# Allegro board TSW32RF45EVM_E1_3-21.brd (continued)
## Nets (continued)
TAA-: C2.2 L6.2 L13.1
TB+: C433.1 R9.2
TB-: C434.1 R10.2
TBB+: C10.1 L8.2 L11.1
TBB-: C10.2 L9.2 L12.1
U17_BYPASS: R157.1 R159.2
USBDM: C103.1 J11.2(D-) U5.16(USBDM)
USBDP: C104.1 J11.3(D+) U5.15(USBDP)
VCM: C61.1 TP2.1(TP) U1.22(VCM)
Y2_N: R80.1 R81.1 Y1.4(OUT_N)
Y2_P: R72.1 R73.1 Y1.5(OUT_P)
YO2_N: C84.1 R80.2
YO2_P: C81.1 R72.2
N19631466: C166.1 U12.14(NR)
N19631491: R127.2 U12.8(1P6V)
N19631493: R125.2 U12.11(0P2V)
N19631495: R124.2 U12.12(0P1V)
N19631505: R126.2 U12.10(0P4V)
N19879131: J11.4(ID) R96.2
N19879145: FB12.2 J11.1(VBUS)
N19879167: C101.1 C102.1 FB12.1 R95.2 TP4.1(TP) U5.20(VCC)
N19879302: U5.11(D3) U13.10(B4)
N19879304: U5.3(D2) U13.11(B3)
N19881704: J10.C18 R88.2
N19881714: J10.H2 R89.1
N19881723: D5.1(ANODE) R88.1
N19884870: C77.2 C78.2 C79.2 C80.2 FB1.1 Y1.6(VDD)
N19884947: SJP1.2(PIN2) Y1.2(NC)
N19886018: C9.1 R64.1 U3.16(DCLKOUT2N)
N19886020: C8.1 R63.1 U3.15(DCLKOUT2P)
N19887754: FB8.2 U3.42(VCC8_OSCIN)
N19887756: C93.2 C94.2 C95.2 FB6.2 FB7.1 FB8.1 FB9.1 U3.47(VCC10_PLL2)
N19887760: C98.2 FB10.2 U3.53(VCC11_CG3)
N19887762: C99.2 FB11.2 U3.64(VCC12_CG0)
N19887789: R86.2 U3.31(STATUS_LD1)
N19887795: R87.2 U3.48(STATUS_LD2)
N19887804: R85.2 U3.59(CLKIN_SEL1)
N19887822: R84.2 U3.58(CLKIN_SEL0)
N19887828: C96.1 U3.12(LDOBYP2)
N19887830: C97.1 U3.11(LDOBYP1)
N19887836: C87.2 C88.2 C89.2 FB2.2 U3.10(VCC1_VCO) U3.33(VCC5_DIG) U3.36(VCC6_PLL1)
N19887876: FB7.2 U3.39(VCC7_OSCOUT)
N19887878: FB9.2 U3.45(VCC9_CP2)
N19887910: C91.2 FB4.2 U3.21(VCC3_SYSREF)
N19887912: C90.2 FB3.2 U3.17(VCC2_CG1)
N19887930: C92.2 FB5.2 U3.26(VCC4_CG2)
N19893167: C372.1 T5.3(SEC)
N19893194: C373.1 T5.1(SEC DOT)
N19893222: C28.2 T5.4(PRI)
N19893438: C33.1 T5.2(NC)
N19895463: C372.2 U8.4(RF2)
N19895477: C373.2 U7.4(RF2)
N19955835: Q1.4(G) U15.4(GATE)
N20015888: C170.2 J13.1(CENTER)
N20015984: C171.2 J9.1(CENTER)
N20042801: R139.2 U16.7(200MV)
N20043120: R138.2 U16.6(100MV)
N20043460: R140.2 U16.9(400MV)
N20043630: R141.2 U16.10(800MV)
N20048856: R137.2 U16.4(PG)
N20080651: C368.1 SJP5.2(PIN2) U13.1(VCCA) U13.8(OE)
N20101312: R132.2 R134.1 U14.3(FB)
N20101314: L1.1 U14.6(SW)
N20101373: R136.2 U14.2(PG)
N20111831: R154.2 R155.1 U11.3(FB)
N20111833: L2.1 U11.6(SW)
N20111884: R153.2 U11.2(PG)
N20113513: C193.1 C197.1 R143.1 R158.2 U17.1(OUT4) U17.18(OUT1) U17.19(OUT2) U17.20(OUT3)
N20113515: C193.2 R143.2 R145.1 U17.16(FB/SNS)
N20114896: C204.1 FB19.1 L3.2 R146.1 R148.1 U18.4(VOS)
N20114915: R146.2 R147.1 U18.3(FB)
N20114917: L3.1 U18.6(SW)
N20114968: R148.2 U18.2(PG)
N20121078: FB17.1 R158.1 R159.1
N20150497: SJP2.2(PIN2) U16.14(EN)
N20151052: SJP3.2(PIN2) U17.11(EN)
N20152729: SJP4.2(PIN2) U18.1(EN)
N20210385: R40.2 R165.2 TP8.1(TP) U1.20(CTRL1)
N20210389: R40.1 R164.2 TP9.1(TP) U1.21(CTRL2)
N20213760: R33.2 SW1.1
N20220969: C387.1 U9.14(NR)
N20220990: R171.2 U9.8(1P6V)
N20220992: R172.2 U9.11(0P2V)
N20220994: R170.2 U9.12(0P1V)
N20221006: R173.2 U9.10(0P4V)
N20227487: C399.1 C400.2 U10.27(VBIASBANK)
N20231187: C403.2 U10.3(VBIASVCO)
N20232417: C404.2 U10.38(VREGVCO)
N20232915: C405.2 U10.29(VREFVCO#29)
N20233092: C406.2 U10.36(VREFVCO#36)
N20234062: C407.2 U10.33(VBIASVARAC)
N20235277: C409.1 R175.1 U10.23(RFOUTAP)
N20235286: C410.1 R176.1 U10.22(RFOUTAM)
N20237052: C412.1 R177.1 U10.18(RFOUTBP)
N20237066: C413.1 R178.1 U10.19(RFOUTBM)
N20239082: R179.2 U10.30(REXT)
N20249678: C391.2 U10.10(VCCIN)
N20251064: C394.2 R174.1
N20251377: C420.1 R182.2 R183.1
N20251505: C421.1 R183.2 U10.35(VTUNE)
N20257347: R184.1 R185.2 U10.20(MUXOUT)
N20258125: D7.1(ANODE) R185.1
N20306930: C429.1 U8.6(RFC)
N20306944: C430.1 U7.6(RFC)
N20361040: C36.1 U4.14(NR)
N20361065: R11.2 U4.12(0P1V)
N20361077: R12.2 U4.10(0P4V)
N20361858: R14.2 U4.6(3P2V)
N20361961: R13.2 U4.9(0P8V)
N20445187: C437.2 R6.2
N20459699: C433.2 L8.1
N20459721: C434.2 L9.1
N20459741: C435.2 L5.1
N20459761: C436.2 L6.1
N20460250: C438.2 R193.2
N20460913: C439.2 R194.2
N20461153: C440.2 R1.2
N183394940: D6.1(ANODE) R133.2
N198851401: C71.2 R54.1
N198852420: C70.2 R47.1

Pads without a net: J10 A22 A23 A26 A27 A30 A31 A34 A35 A38 A39 B1 B4 B5 B8 B9 B20 B21 B24 B25 B28 B29 B32 B33 B36 B37 B40 C2 C3 C10 C11 C14 C15 C19 C22 C23 C30 C31 C34 C35 C37 C39 D1 D8 D9 D11 D12 D14 D15 D17 D18 D20 D21 D23 D24 D26 D27 D29 D30 D31 D32 D33 D34 D35 D36 D38 D40 E2 E3 E6 E7 E9 E10 E12 E13 E15 E16 E18 E19 E21 E22 E24 E25 E27 E28 E30 E31 E33 E34 E36 E37 E39 F1 F4 F5 F7 F8 F10 F11 F13 F14 F16 F17 F19 F20 F22 F23 F25 F26 F28 F29 F31 F32 F34 F35 F37 F38 F40 G2 G3 G15 G16 G18 G19 G21 G22 G24 G25 G27 G28 G30 G31 G33 G34 G36 G37 G39 H1 H4 H5 H7 H8 H10 H11 H13 H14 H16 H17 H19 H20 H22 H23 H25 H26 H28 H29 H31 H32 H34 H35 H37 H38 H40 J2 J3 J6 J7 J9 J10 J12 J13 J15 J16 J18 J19 J21 J22 J24 J25 J27 J28 J30 J31 J33 J34 J36 J37 J39 K1 K4 K5 K7 K8 K10 K11 K13 K14 K16 K17 K19 K20 K22 K23 K25 K26 K28 K29 K31 K32 K34 K35 K37 K38 K40; U3 7 8 9 22 23 24 25 27 28 29 30 37 38 49 50 51 52 56 57 60 61; U4 2 4 5 8 11 17 18 19; U5 8 12 13 14 19 22 23 24 27 28; U9 2 4 5 6 9 17 18 19; U10 5 28 32; U12 2 4 5 6 9 17 18 19; U13 6 9; U15 1 3; U16 3 5 11 12 13; U17 2 3 4 9 13 14 15 17

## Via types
v1: diameter 0.457, hole 0.203, TOP to BOTTOM, 2207 vias
v2: diameter 0.305, hole 0.152, TOP to BOTTOM, 175 vias
v3: diameter 0.559, hole 0.305, TOP to BOTTOM, 511 vias
v4: diameter 0.508, hole 0.254, TOP to BOTTOM, 139 vias
v5: diameter 0.762, hole 0.381, TOP to BOTTOM, 8 vias
v6: diameter 0.61, hole 0.33, TOP to BOTTOM, 16 vias

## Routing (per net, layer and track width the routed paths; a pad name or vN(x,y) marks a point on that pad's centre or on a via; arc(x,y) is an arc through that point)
1.4V: length 24.1
  TOP w0.305: v1(75.16,4.98) 74.78,5.35 U11.4
  TOP w0.508: v1(75.16,4.98) 75.32,4.82 R154.1 v1(75.32,4.07) 75.55,3.84 v1(76.63,3.84)
  BOTTOM w0.432: 80.44,10.24 TP13.1 ; TP13.1 79.53,10.54 ; TP13.1 81.36,10.54 ; TP13.1 79.22,11.46 ; TP13.1 81.36,12.37 ; TP13.1 79.53,12.37 ; TP13.1 81.66,11.46 ; TP13.1 80.44,12.68
  BOTTOM w0.762: v1(76.3,11.23) 74.75,11.23 74.09,10.57 74.09,5.99 75.11,4.98 v1(75.16,4.98) 75.16,4.23 v1(75.32,4.07) 75.55,3.84 v1(76.63,3.84)
  vias: v1(76.33,14.12) v1(76.3,13.41) v1(76.33,12.74) v1(76.3,11.96) v1(77.22,14.12) v1(77.19,13.41) v1(77.22,12.74) v1(77.19,11.96) v1(77.19,11.23) v1(78.21,13.41) v1(78.21,11.96) v1(78.21,11.23) v1(78.23,14.12) v1(78.23,12.74) v1(84.2,15.67)
3.3VUSB: length 18.1
  BOTTOM w0.305: U13.14 50.69,24.99 49.33,24.99 48.16,23.83 48.16,21.21 47.72,20.77 U5.4
  BOTTOM w0.381: U5.17 40.29,15.57 v1(40.44,15.42) 40.72,15.42 44.63,19.33 44.63,20.39 45.01,20.77 U5.4
  vias: v1(50.72,24.96)
5.0V_IN: length 92.9
  TOP w0.127: v3(44.65,7.3) 44.65,8.27 v3(44.64,8.28) ; v3(44.65,7.3) v3(45.65,7.3) ; v3(44.65,7.3) v3(43.65,7.3) ; v3(45.65,7.3) v3(46.65,7.3) v3(46.65,8.3) ; v3(45.65,7.3) v3(45.65,8.3) ; v3(46.65,8.3) v3(45.65,8.3) ; v3(46.65,8.3) v3(46.65,9.3) ; v3(45.65,8.3) 45.63,8.28 v3(44.64,8.28) ; v3(45.65,8.3) v3(45.65,9.3) ; v3(42.65,8.3) v3(42.65,7.3) v3(43.65,7.3) ; v3(42.65,8.3) v3(42.65,9.3) ; v3(42.65,8.3) v3(43.65,8.3) ; v3(46.65,9.3) 46.56,9.39 Q1.5 ; v3(46.65,9.3) v3(45.65,9.3) ; v3(44.64,8.28) 44.62,8.3 v3(43.65,8.3) ; v3(44.64,8.28) 44.64,9.29 v3(44.65,9.3) ; v3(43.65,7.3) v3(43.65,8.3) ; v3(42.65,9.3) 42.75,9.39 Q1.8 ; v3(42.65,9.3) v3(43.65,9.3) ; v3(43.65,9.3) v3(44.65,9.3) ; v3(43.65,9.3) v3(43.65,8.3) ; v3(45.65,9.3) v3(44.65,9.3)
  TOP w0.432: TP17.1 41.04,7.73 ; TP17.1 38.67,10.1 ; TP17.1 41.45,8.92 ; TP17.1 38.25,8.92 ; TP17.1 39.85,7.31 ; TP17.1 41.04,10.1 ; TP17.1 38.67,7.73 ; TP17.1 39.85,10.52 ; 34.92,5.44 J8.1 ; J8.1 33.04,6.14 ; J8.1 36.81,6.14 ; J8.1 32.33,8.03 ; J8.1 37.52,8.03 ; J8.1 33.04,9.91 ; J8.1 34.92,10.62 ; J8.1 36.81,9.91
  BOTTOM w0.432: J8.1 34.92,10.62 ; J8.1 33.04,9.91 ; J8.1 33.04,6.14 ; J8.1 37.52,8.03 ; J8.1 32.33,8.03 ; J8.1 36.81,9.91 ; J8.1 34.92,5.44 ; J8.1 36.81,6.14 ; 38.67,7.73 TP17.1 ; TP17.1 39.85,7.31 ; TP17.1 38.67,10.1 ; TP17.1 38.25,8.92 ; TP17.1 41.04,10.1 ; TP17.1 39.85,10.52 ; TP17.1 41.45,8.92 ; TP17.1 41.04,7.73
5VIN: length 13.1
  TOP w0.305: U14.1 58.22,6.65 U14.7 58.35,6.8 57.66,7.49 ; U18.7 97.34,10.59 C203.1 ; U11.1 73.28,6.25 73.43,6.4 U11.7 73.43,9.22 C121.1
  BOTTOM w0.254: 131.95,4.45 131.9,4.5
  BOTTOM w0.305: U12.13 123.39,4.75 123.22,4.57 ; U17.10 v1(83.13,14.41) ; 131.9,4.5 131.9,5.78 U4.13
  vias: v1(35.46,16.08) v1(35.46,15.32) v1(36.12,16.08) v1(36.12,15.32) v1(36.8,16.08) v1(36.78,15.32) v1(56.97,8.31) v1(56.97,7.47) v1(56.97,6.68) v1(57,5.77) v1(56.97,4.93) v1(57.04,9.15) v1(57.91,8.31) v1(57.91,7.47) v1(57.91,6.68) v1(57.91,5.77) v1(57.89,4.93) v1(57.93,9.15) v1(72.19,9.6) v1(72.19,8.71) v1(72.19,7.87) v1(72.19,7.09) v1(72.19,6.22) v1(72.16,5.38) v1(73.03,8.71) v1(73.03,7.87) v1(73.03,7.09) v1(73.03,6.22) v1(73,5.38) v1(73.05,9.58) v1(81.2,13.74) v1(94.77,5.79) v1(95.4,11) v1(95.4,10.11) v1(95.4,9.22) v1(95.4,8.33) v1(96.11,8.38) v1(96.18,10.98) v1(96.16,10.11) v1(96.16,9.22) v1(96.82,8.38) v1(96.9,10.98) v1(96.93,10.11) v1(96.93,9.22) v1(106.5,7.82) v1(106.5,7.16) v1(106.48,6.48) v1(107.16,8.33) v1(107.16,7.67) v1(107.14,6.99) v1(107.14,6.27) v1(107.82,6.5) v1(107.85,7.85) v1(107.85,7.19) v1(119.18,6.5) v1(119.18,5.84) v1(119.15,5.16) v1(119.81,5.66) v1(119.81,4.95) v1(119.84,7.01) v1(119.84,6.35) v1(120.52,6.53) v1(120.52,5.87) v1(120.5,5.18) v1(128.83,5.61) v1(128.83,4.95) v1(128.8,4.27) v1(129.49,6.12) v1(129.49,5.46) v1(129.46,4.78) v1(129.46,4.06) v1(130.18,5.64) v1(130.18,4.98) v1(130.15,4.29) v3(42.6,3.91) v3(42.6,3.12) v3(42.72,5.49) v3(42.7,4.72) v3(43.51,5.49) v3(43.51,4.72) v3(43.54,3.91) v3(43.54,3.12) v3(44.32,4.72) v3(44.37,5.49) v3(44.37,3.91) v3(44.37,3.12) v3(45.29,5.51) v3(45.26,4.7) v3(45.26,3.91) v3(45.26,3.12) v3(50.72,3.84) v3(50.75,4.83) v3(51.64,4.83) v3(51.64,3.84) v3(52.53,4.83) v3(52.53,3.84)
+1.9V: length 8.2
  TOP w0.508: FB20.3 62.61,27.69 62.18,28.12 SJP5.3
+2.2V: length 33.9
  TOP w0.305: v1(60.07,4.5) 59.72,4.85 U14.4
  TOP w0.432: TP15.1 64.06,14.25 ; TP15.1 63.15,12.12 ; TP15.1 62.84,13.03 ; TP15.1 64.06,11.81 ; TP15.1 63.15,13.94 ; TP15.1 65.28,13.03 ; TP15.1 64.97,12.12 ; TP15.1 64.97,13.94
  TOP w0.508: v1(60.07,4.5) 60.2,4.37 v1(60.2,3.66) ; v1(60.2,3.66) v1(60.71,3.66) ; v1(60.2,3.66) 60.23,3.69 v1(61.28,3.69)
  BOTTOM w0.432: TP15.1 64.06,14.25 ; TP15.1 64.97,13.94 ; TP15.1 63.15,12.12 ; TP15.1 63.15,13.94 ; TP15.1 64.97,12.12 ; TP15.1 65.28,13.03 ; TP15.1 64.06,11.81 ; TP15.1 62.84,13.03
  BOTTOM w0.762: v1(61.09,10.92) 59.69,10.92 58.9,10.13 58.9,6.38 60.07,5.21 v1(60.07,4.5) 60.2,4.37 v1(60.2,3.66) v1(60.71,3.66) 60.73,3.69 v1(61.28,3.69)
  vias: v1(61.09,13.97) v1(61.09,13.21) v1(61.09,12.45) v1(61.09,11.68) v1(61.85,13.97) v1(61.85,13.21) v1(61.85,12.45) v1(61.85,11.68) v1(61.85,10.92) v1(62.61,13.97) v1(62.61,13.21) v1(62.61,12.45) v1(62.61,11.68) v1(62.61,10.92) v1(65.38,15.04)
+3.3V_LMX: length 26.3
  TOP w0.305: v2(55.35,61.7) v2(54.64,61.7) ; v2(58.78,64.11) 58.76,64.12 v2(58.76,64.47) 58.75,64.48 v2(58.75,64.85) ; v2(55.35,59.18) 55.34,59.19 v2(54.99,59.19) 54.65,59.19 v2(54.64,59.18) ; v2(61.39,60.68) v2(60.68,60.68) ; v2(60.25,58.72) v2(60.25,58.39) v2(60.25,58.06)
  TOP w0.432: 113.77,24.05 TP10.1 ; TP10.1 112.85,24.36 ; TP10.1 113.77,26.49 ; TP10.1 114.68,26.19 ; TP10.1 112.55,25.27 ; TP10.1 114.99,25.27 ; TP10.1 112.85,26.19 ; TP10.1 114.68,24.36
  TOP w0.508: C398.2 58.17,58.6 58.17,57.79 v1(58.62,57.43)
  L3_PWR w0.432: 112.85,26.19 TP10.1 ; TP10.1 112.55,25.27 ; TP10.1 114.99,25.27 ; TP10.1 114.68,24.36 ; TP10.1 112.85,24.36 ; TP10.1 113.77,24.05 ; TP10.1 114.68,26.19 ; TP10.1 113.77,26.49
  BOTTOM w0.305: v1(58.62,57.43) 58.26,57.79 v2(58.26,58.42)
  vias: v1(64.29,63.7) v1(112.27,25.78) v1(112.27,24.89) v1(112.27,24) v1(112.39,26.8) v1(113.28,26.8) v1(114.68,26.67) v1(115.57,26.67) v1(115.57,25.78) v1(115.57,24.89) v1(116.46,26.67) v1(116.46,25.78) v2(54.99,61.69) v2(58.27,58.78) v2(61.04,60.69)
+3.3V_LMXRF: length 1.5
  TOP w0.305: v2(56.03,56.18) 56.08,56.13 C411.1 56.9,56.13 v2(56.95,56.18)
  BOTTOM w0.305: R178.2 v2(56.03,56.18) ; R177.2 v2(56.95,56.18) v1(56.49,56.18)
  vias: v1(38.61,62.13) v1(38.61,61.37) v1(39.24,62.33) v1(39.88,62.13) v1(39.88,61.37) v1(53.06,59.92) v1(109.09,25.15) v1(109.09,24.26) v1(109.09,23.37) v1(109.98,25.15) v1(109.98,24.26) v1(109.98,23.37) v1(110.87,25.15) v1(110.87,24.26) v1(110.87,23.37) v2(53.06,60.38) v2(53.06,59.46)
+3.3VCLK: length 28.9
  TOP w0.432: TP12.1 127.15,21.61 ; TP12.1 126.24,21.92 ; TP12.1 125.02,20.7 ; TP12.1 125.32,19.79 ; TP12.1 127.15,19.79 ; TP12.1 125.32,21.61 ; TP12.1 126.24,19.48
  L6_PWR w0.432: TP12.1 126.24,21.92 ; TP12.1 126.24,19.48 ; TP12.1 127.46,20.7 ; TP12.1 125.32,21.61 ; TP12.1 127.15,21.61 ; TP12.1 125.02,20.7 ; TP12.1 125.32,19.79 ; TP12.1 127.15,19.79
  BOTTOM w0.432: TP12.1 127.15,19.79 ; TP12.1 127.15,21.61 ; TP12.1 125.32,21.61 ; TP12.1 126.24,19.48 ; TP12.1 126.24,21.92 ; TP12.1 127.46,20.7 ; TP12.1 125.02,20.7 ; TP12.1 125.32,19.79
  vias: v1(86.41,54.33) v1(86.39,53.59) v1(86.74,58.67) v1(86.74,58.04) v1(86.74,55.6) v1(86.74,54.99) v1(87.1,54.33) v1(87.07,53.59) v1(87.38,58.67) v1(87.38,58.06) v1(87.38,55.6) v1(87.38,54.99) v1(91.11,64.77) v1(91.14,65.46) v1(91.72,64.74) v1(91.74,65.46) v1(92.3,65.48) v1(92.28,64.72) v1(100.51,60.58) v1(100.48,60.03) v1(100.53,61.19) v1(100.53,52.37) v1(101.22,61.17) v1(101.22,60.56) v1(101.24,60) v1(101.83,52.98) v1(101.78,51.82) v1(102.41,52.98) v1(102.41,52.37) v1(102.44,51.82) v1(103.54,65.42) v1(103.54,63.17) v1(111.56,65.76) v1(111.56,64.9) v1(112.14,65.33) v1(112.7,65.76) v1(112.7,64.9) v1(118.24,58.7) v1(123.57,22.73) v1(123.57,22.1) v1(123.57,21.46) v1(124.21,22.73) v1(124.21,22.1) v1(124.21,21.46) v1(124.84,22.73) v1(124.84,22.1) v1(124.84,21.46) v1(125.48,22.73) v1(125.48,22.1)
+4.5V: length 19.6
  TOP w0.508: L14.1 v1(23.62,37.34) ; L4.1 v1(23.62,48.13)
  L6_PWR w0.432: 133.07,21.61 TP1.1 ; TP1.1 133.99,19.48 ; TP1.1 134.9,21.61 ; TP1.1 132.77,20.7 ; TP1.1 134.9,19.79 ; TP1.1 133.99,21.92 ; TP1.1 133.07,19.79 ; TP1.1 135.2,20.7
  BOTTOM w0.432: TP1.1 134.9,21.61 ; TP1.1 133.07,21.61 ; TP1.1 133.99,21.92 ; TP1.1 134.9,19.79 ; TP1.1 133.99,19.48 ; TP1.1 133.07,19.79 ; TP1.1 132.77,20.7
  vias: v1(21.34,46.48) v1(21.34,38.99) v1(131.32,23.75) v1(131.32,23.24) v1(131.57,22.35) v1(131.72,21.36) v1(131.65,18.9) v1(131.65,18.08) v1(131.83,20.17) v1(132.21,18.9) v1(132.21,18.08) v1(132.33,23.5) v1(132.46,22.73) v1(132.46,22.1) v1(132.46,21.34) v1(133.48,23.5) v1(133.48,22.73) v1(133.48,22.1) v1(133.68,18.9) v1(133.68,18.08) v1(134.24,24.51) v1(134.24,23.5) v1(134.24,22.73) v1(134.24,18.9) v1(134.24,18.08) v1(134.87,24.51) v1(134.87,23.5) v1(134.87,22.1)
AVDD1.9V: length 49.5
  TOP w0.254: U1.39 38.99,37.14 v2(38.84,36.98) v2(38.53,36.68) 38.53,36.32 v1(38.58,36.37) ; U1.24 v2(36.88,44.49) 35.88,44.49 v1(35.81,44.55) ; v2(41.99,37.36) U1.45 41.99,37.97 v2(41.96,38) ; v1(35.79,40.84) 35.94,41 v2(36.22,41) U1.31 ; v1(38.79,49.07) 38.99,48.87 v2(38.99,48.69) U1.16 ; v2(42.21,48.46) 41.99,48.24 U1.10 ; v2(42.57,36.78) v1(42.57,36.27)
  TOP w0.305: v1(41.94,49.2) 42.21,48.92 v2(42.21,48.82) v2(42.21,48.46) ; v2(41.99,37.36) v1(42.26,37.08) v2(42.27,37.08) v2(42.57,36.78)
  TOP w0.432: 65.66,22.28 TP20.1 ; TP20.1 65.66,24.71 ; TP20.1 64.44,23.5 ; TP20.1 66.57,22.58 ; TP20.1 66.88,23.5 ; TP20.1 64.75,24.41 ; TP20.1 66.57,24.41 ; TP20.1 64.75,22.58
  L3_PWR w0.432: 64.75,24.41 TP20.1 ; TP20.1 64.44,23.5 ; TP20.1 66.57,22.58 ; TP20.1 66.57,24.41 ; TP20.1 66.88,23.5 ; TP20.1 64.75,22.58 ; TP20.1 65.66,22.28 ; TP20.1 65.66,24.71
  BOTTOM w0.305: v2(37.49,44.49) v2(36.88,44.49) 36.36,44.49 v2(36.35,44.5) 35.86,44.5 v1(35.81,44.55) ; v1(41.94,49.2) 42.21,48.92 v2(42.21,48.82) v2(42.21,48.46) ; v1(42.57,36.27) v2(42.57,36.78) v2(42.27,37.08) v1(42.26,37.08) v2(41.99,37.36) 41.96,37.39 v2(41.96,38) ; v1(38.58,36.37) 38.53,36.32 v2(38.53,36.68) v2(38.84,36.98) 38.99,37.13 v2(38.99,37.49) v2(38.99,38) ; v1(35.79,40.84) 35.94,41 v2(36.22,41) v2(36.63,41) v2(37.08,41) v2(37.49,41) ; v1(38.79,49.07) 38.99,48.87 v2(38.99,48.69) v2(38.99,48.26)
  BOTTOM w0.432: 64.44,23.5 TP20.1 ; TP20.1 66.57,22.58 ; TP20.1 64.75,24.41 ; TP20.1 66.88,23.5 ; TP20.1 65.66,22.28 ; TP20.1 66.57,24.41 ; TP20.1 64.75,22.58 ; TP20.1 65.66,24.71
  vias: v1(33.91,38.86) v1(33.91,36.63) v1(62.48,24.38) v1(62.48,23.62) v1(62.48,22.86) v1(62.48,22.1) v1(63.25,24.38) v1(63.25,23.62) v1(63.25,22.86) v1(63.25,22.1) v1(64.01,24.38) v1(64.01,23.62) v1(64.01,22.86) v1(64.01,22.1)
AVDD1.15V: length 49.6
  TOP w0.254: v1(37.82,36.37) v2(37.82,36.65) ; U1.30 v2(36.25,41.48) 35.92,41.48 v1(35.79,41.61) ; v1(42.7,49.2) 42.72,49.17 v2(42.72,48.79) ; v2(41.81,36.73) v1(41.81,36.27) ; U1.38 v2(38.49,37.56) 37.93,36.98 v2(37.82,36.98) ; U1.44 v2(41.49,37.05) ; U1.46 v2(42.49,38.07) ; U1.25 v2(36.88,43.99) 36.01,43.99 v1(35.81,43.79) ; v2(42.7,48.41) 42.7,48.36 42.49,48.15 U1.9
  TOP w0.305: U1.17 v2(38.49,48.17) v2(38.02,48.64) v1(38.02,49.07) ; v2(42.7,48.41) 42.72,48.44 v2(42.72,48.79) ; v2(37.82,36.65) v2(37.82,36.98) ; v2(41.49,37.05) v2(41.81,36.73)
  L6_PWR w0.152: v2(42.49,38.07) 42.49,38.18 42.8,38.48 42.8,39.37
  L6_PWR w0.305: v2(42.49,38.07) v2(42.49,37.69)
  L6_PWR w0.432: TP22.1 85.65,23.14 ; TP22.1 83.21,23.14 ; TP22.1 84.43,24.36 ; TP22.1 85.34,24.06 ; TP22.1 83.51,24.06 ; TP22.1 83.51,22.23 ; TP22.1 85.34,22.23 ; TP22.1 84.43,21.92
  BOTTOM w0.305: v2(38.48,37.97) 38.49,37.96 v2(38.49,37.56) 38.49,37.55 v2(38.2,37.26) 37.92,36.98 v2(37.82,36.98) v2(37.82,36.65) v1(37.82,36.37) ; 41.24,37.3 41.28,37.34 41.28,37.97 ; 41.24,37.3 v2(41.49,37.05) ; 41.24,37.3 41.02,37.52 v2(41.02,37.69) 41.02,38 41.05,37.97 41.28,37.97 ; v2(37.49,43.99) v2(36.88,43.99) 36.88,43.99 v2(36.35,43.99) 36.02,43.99 v1(35.81,43.79) ; 41.28,37.97 v2(41.48,37.97) v2(41.48,37.49) 41.49,37.48 v2(41.49,37.05) ; v2(41.49,37.05) v2(41.81,36.73) v1(41.81,36.27) ; v1(35.79,41.61) 35.92,41.48 v2(36.25,41.48) v2(36.7,41.48) v2(37.11,41.48) v2(37.49,41.48) ; 39.55,47.47 38.89,47.47 38.49,47.87 v2(38.49,48.17) v2(38.02,48.64) v1(38.02,49.07) ; 39.55,47.47 40.97,47.47 41,47.45 v2(41,47.78) v2(39.5,47.78) 39.5,47.52 39.55,47.47 ; v2(42.49,37.69) 42.49,38.05 C47.1 ; v2(39.47,37.67) 39.47,38.02 v2(39.52,38.07) ; v1(42.7,49.2) 42.72,49.17 v2(42.72,48.79) 42.7,48.77 v2(42.7,48.41)
  BOTTOM w0.432: 83.51,22.23 TP22.1 ; TP22.1 83.21,23.14 ; TP22.1 83.51,24.06 ; TP22.1 85.34,22.23 ; TP22.1 85.34,24.06 ; TP22.1 85.65,23.14 ; TP22.1 84.43,21.92 ; TP22.1 84.43,24.36
  vias: v1(83.16,21.49) v1(84.05,21.49) v1(84.94,21.49) v1(85.98,23.27) v1(85.95,22.38) v1(85.95,21.49) v1(86.87,23.27) v1(86.84,22.38) v1(86.84,21.49) v2(39.55,47.42) v2(41,47.4) v2(41,38.07)
DVDD1.15V: length 82.3
  TOP w0.254: v1(43.46,49.2) 43.41,49.15 v2(43.41,48.77) ; v2(43.38,48.36) 42.99,47.97 U1.8 ; v2(45.34,48.26) 44.99,47.91 U1.4 ; v1(43.33,36.27) v2(43.33,36.7) ; v2(43.18,37.34) 42.99,37.53 v2(42.99,37.84) ; U1.64 v2(46.89,42.98)
  TOP w0.305: v1(45.44,49.07) 45.38,49.01 45.38,48.73 45.34,48.69 v2(45.34,48.62) v2(45.34,48.26) ; v2(46.89,46) U1.70 47.84,45.99 v1(47.85,45.97) ; U1.51 44.99,37.38 v2(45.19,37.19) v2(45.19,36.78) 45.19,36.3 v1(45.21,36.27) ; v2(43.33,36.7) 43.18,36.86 v2(43.18,37.01) v2(43.18,37.34) ; v2(43.38,48.36) 43.41,48.39 v2(43.41,48.77)
  TOP w0.381: v1(47.78,42.98) v2(47.29,42.98) v2(46.89,42.98) ; U1.57 v2(46.95,39.49)
  TOP w0.432: TP5.1 100.43,20.65 ; TP5.1 99.52,20.34 ; TP5.1 99.52,22.78 ; TP5.1 100.74,21.56 ; TP5.1 98.6,20.65 ; TP5.1 98.6,22.48 ; TP5.1 100.43,22.48 ; TP5.1 98.3,21.56
  TOP w0.762: v1(98.42,20.12) 98.22,20.32 94.23,20.32 92.2,18.29 92.2,8.64 90.93,7.37 88.27,7.37 86.74,5.84 v1(84.48,5.84)
  L6_PWR w0.305: v2(43.18,37.34) 43.18,37.65 v2(42.99,37.84) 43.3,37.84 43.56,38.1
  L6_PWR w0.432: 98.6,22.48 TP5.1 ; TP5.1 99.52,20.34 ; TP5.1 100.43,22.48 ; TP5.1 99.52,22.78 ; TP5.1 100.74,21.56 ; TP5.1 100.43,20.65 ; TP5.1 98.6,20.65 ; TP5.1 98.3,21.56 ; JP1.1 93.98,27.97 ; JP1.1 92.81,26.8 ; JP1.1 93.1,25.92 ; JP1.1 95.15,26.8 ; JP1.1 94.86,25.92 ; JP1.1 93.98,25.63 ; JP1.1 93.1,27.67 ; JP1.1 94.86,27.67
  BOTTOM w0.305: v2(46.89,42.98) v2(47.29,42.98) ; v2(43.38,48.36) 43.38,48.74 v2(43.41,48.77) 43.41,49.15 v1(43.46,49.2) ; v2(45.34,48.26) v2(45.34,48.62) 45.34,48.97 v1(45.44,49.07) ; v1(45.21,36.27) 45.19,36.3 v2(45.19,36.78) v2(45.19,37.19) ; v2(42.99,37.84) 42.99,37.53 v2(43.18,37.34) v2(43.18,37.01) 43.18,36.86 v2(43.33,36.7) v1(43.33,36.27)
  BOTTOM w0.381: v2(47.29,39.5) 47.28,39.49 v2(46.95,39.49) ; v2(47.29,42.98) v1(47.78,42.98) ; v1(47.85,45.97) v2(47.29,45.97) 46.91,45.97 v2(46.89,46)
  BOTTOM w0.432: 99.52,20.34 TP5.1 ; TP5.1 100.74,21.56 ; TP5.1 99.52,22.78 ; TP5.1 98.6,20.65 ; TP5.1 98.6,22.48 ; TP5.1 98.3,21.56 ; TP5.1 100.43,22.48 ; TP5.1 100.43,20.65
  vias: v1(44.27,35.13) v1(44.35,50.18) v1(53.24,27.48) v1(53.24,26.8) v1(53.9,27.48) v1(53.9,26.8) v1(98.4,19.3) v1(98.4,18.49) v1(99.21,19.3) v1(99.21,18.49) v1(99.24,20.12) v1(100.08,20.12) v1(100.05,19.3) v1(100.05,18.49)
GND: length 2671.2
  TOP w0.127: 46.64,44.49 U1.67 ; v3(43.56,44.05) v3(42.24,42.74) ; v3(46.19,40.11) v3(44.87,40.11) ; v3(40.93,41.42) 39.99,40.49 U1.32 ; 39.99,44.99 v3(40.93,44.05) ; 45.47,38.48 45.49,38.46 ; 45.49,45.99 v3(44.87,45.37)
  TOP w0.152: U8.2 v2(32.64,44.53)
  TOP w0.203: v3(46.19,38.79) 47.23,37.74 v1(47.37,37.74) ; 46.61,44.45 46.64,44.49 ; U1.26 41.49,43.49 v3(42.24,42.74) 41.49,41.99 U1.29 ; v2(32.64,44.53) 32.72,44.53 32.77,44.48 33.2,44.48 ; 45.49,38.46 U1.52 ; 32.44,41.81 v2(31.83,41.81) ; U1.3 45.49,45.99 ; U1.23 39.99,44.99
  TOP w0.254: U1.18 37.99,46.99 v3(38.3,46.68) ; U1.60 v1(47.84,40.99) 48.65,40.99 v1(48.95,40.69) ; U1.37 37.99,38.49 v3(38.3,38.79)
  TOP w0.305: C397.2 55.96,59.39 v6(56.49,59.92) ; U2.3 19.68,42.99 v4(19.43,42.74) 19.68,42.49 U2.4 ; v3(38.3,38.79) v3(39.61,40.11) ; v6(56.49,61.95) 56.36,61.95 56.11,61.7 C390.1 ; v3(38.3,46.68) v3(39.61,45.37) ; v1(98.96,9.35) 98.7,9.35 98.54,9.18 U18.5 ; U2.19 23.86,45.32 v2(24.13,45.59) ; U11.5 v1(75.09,7.3) ; U11.5 74.63,6.72 74.78,6.58 v1(75.03,6.58) ; U11.5 74.63,7.88 74.75,8 v1(75.06,8) ; U2.16 25.53,42.99 v4(25.78,42.74) 25.53,42.49 U2.15 ; U2.12 23.86,40.18 v2(24.13,39.9) ; U2.7 v2(21.36,39.9) 21.86,40.4 U2.8 ; U2.24 v2(21.36,45.57) 21.86,45.07 U2.23 ; U14.5 59.68,6.91 v1(59.97,6.91) ; v6(59.54,60.93) 59.79,60.68 C392.2 ; v1(59.97,6.91) v1(59.97,6.4) 59.66,6.71 59.66,7.14 59.94,7.42 v1(59.94,7.44) 59.97,7.42 v1(59.97,6.91) ; v6(59.54,62.97) 59.05,63.45 C401.2 v6(58.52,62.97) ; C94.1 v1(95.91,67.41) ; v1(43.46,49.91) 43.41,49.86 C37.2 41.99,49.86 v1(41.94,49.91) ; U18.5 v1(99.03,8.66) ; U18.5 98.54,8.12 98.7,7.95 v1(98.96,7.95)
  TOP w0.381: R89.2 139.98,58.91 v1(139.7,59.18) ; v1(43.33,35.56) v1(42.57,35.56) v1(41.81,35.56)
  TOP w0.432: 26.34,8.03 J8.2 ; J8.2 31.01,8.03 ; J8.2 30.38,9.73 ; J8.2 30.38,6.32 ; J8.2 28.68,10.36 ; J8.2 26.97,6.32 ; J8.2 28.68,5.69 ; 22.35,29.82 JP5.2 ; JP5.2 23.52,30.99 ; JP5.2 21.47,30.11 ; JP5.2 21.18,30.99 ; JP5.2 23.23,30.11 ; JP5.2 22.35,32.16 ; JP5.2 23.23,31.87 ; JP5.2 21.47,31.87 ; 71.75,66.89 J7.3 ; J7.3 72.97,67.32 ; J7.3 74.2,64.43 ; J7.3 74.64,65.66 ; J7.3 74.2,66.89 ; J7.3 71.75,64.43 ; J7.3 71.31,65.66 ; J7.3 72.97,63.99 ; 48.01,65.05 JP2.1 ; JP2.1 49.17,65.05 ; JP2.1 46.84,67.39 ; JP2.1 48.01,67.39 ; JP2.1 46.84,65.05 ; JP2.1 49.17,67.39 ; JP2.1 49.17,66.22 ; JP2.1 46.84,66.22 ; 16.17,19.39 MT2.1 ; MT2.1 19.99,17.78 ; MT2.1 15.57,17.78 ; MT2.1 17.78,15.57 ; MT2.1 19.39,16.17 ; MT2.1 16.17,16.17 ; MT2.1 17.78,19.99 ; MT2.1 19.39,19.39 ; J9.3 133.37,56.16 ; J9.3 131.03,54.56 ; J9.3 134.29,55.24 ; J9.3 132.01,52.96 ; J9.3 131.46,53.33 ; J9.3 132.69,56.22 ; J9.3 133.92,55.79 ; J9.3 131.09,53.88 ; J9.3 132.01,56.16 ; J9.3 133.37,52.96 ; J9.3 134.29,53.88 ; J9.3 133.92,53.33 ; J9.3 131.09,55.24 ; J9.3 134.35,54.56 ; J9.3 132.69,52.89 ; J9.3 131.46,55.79 ; 126.93,47.88 J9.5 ; J9.5 129.27,49.48 ; J9.5 126.38,50.71 ; J9.5 129.21,50.16 ; J9.5 125.95,49.48 ; J9.5 126.01,50.16 ; J9.5 128.29,47.88 ; J9.5 126.01,48.8 ; J9.5 127.61,47.81 ; J9.5 126.38,48.25 ; J9.5 126.93,51.08 ; J9.5 129.21,48.8 ; J9.5 127.61,51.14 ; J9.5 128.29,51.08 ; J9.5 128.84,50.71 ; J9.5 128.84,48.25 ; J9.4 134.35,49.48 ; J9.4 131.03,49.48 ; J9.4 131.46,48.25 ; J9.4 131.46,50.71 ; J9.4 132.69,47.81 ; J9.4 132.69,51.14 ; J9.4 133.92,50.71 ; TP11.1 117.25,4.34 ; TP11.1 116.33,4.65 ; TP11.1 117.55,3.43 ; TP11.1 117.25,2.52 ; TP11.1 115.42,2.52 ; TP11.1 115.42,4.34 ; TP11.1 116.33,2.21 ; TP11.1 115.11,3.43 ; 17.06,66.51 MT1.1 ; MT1.1 18.67,67.11 ; MT1.1 20.28,63.28 ; MT1.1 20.88,64.9 ; MT1.1 16.46,64.9 ; MT1.1 18.67,62.69 ; MT1.1 17.06,63.28 ; MT1.1 20.28,66.51 ; 40.94,63.35 JP3.2 ; JP3.2 42.11,62.18 ; JP3.2 42.99,62.47 ; JP3.2 41.24,64.22 ; JP3.2 42.99,64.22 ; JP3.2 42.11,64.52 ; JP3.2 43.28,63.35 ; JP3.2 41.24,62.47 ; 122.48,26.16 TP19.1 ; TP19.1 124.92,26.16 ; TP19.1 122.78,25.25 ; TP19.1 122.78,27.08 ; TP19.1 123.7,24.94 ; TP19.1 123.7,27.38 ; TP19.1 124.61,25.25 ; TP19.1 124.61,27.08 ; 99.06,25.63 JP1.3 ; JP1.3 98.18,27.67 ; JP1.3 100.23,26.8 ; JP1.3 99.94,27.67 ; JP1.3 99.06,27.97 ; JP1.3 99.94,25.92 ; JP1.3 97.89,26.8 ; JP1.3 98.18,25.92 ; 131.03,60.27 J13.4 ; J13.4 133.92,61.5 ; J13.4 132.69,61.94 ; J13.4 133.92,59.05 ; J13.4 131.46,61.5 ; J13.4 132.69,58.61 ; J13.4 131.46,59.05 ; J13.4 134.35,60.27 ; 103.81,22.61 TP6.1 ; TP6.1 104.12,23.52 ; TP6.1 104.12,21.69 ; TP6.1 105.94,21.69 ; TP6.1 106.25,22.61 ; TP6.1 105.94,23.52 ; TP6.1 105.03,21.39 ; TP6.1 105.03,23.83 ; 31.93,0.89 J8.3 ; J8.3 34.27,3.23 ; J8.3 30.22,1.52 ; J8.3 33.63,1.52 ; J8.3 30.22,4.93 ; J8.3 29.59,3.23 ; J7.4 74.2,59.35 ; J7.4 71.75,61.81 ; J7.4 71.31,60.58 ; J7.4 74.2,61.81 ; J7.4 72.97,62.24 ; J7.4 71.75,59.35 ; J7.4 74.64,60.58 ; 21.18,54.48 22.35,54.48 ; 22.35,54.48 22.35,55.65 ; 22.35,54.48 23.23,55.36 ; 22.35,54.48 21.47,53.61 ; 22.35,54.48 23.23,53.61 ; 22.35,54.48 21.47,55.36 ; 22.35,54.48 23.52,54.48 ; 22.35,54.48 22.35,53.31 ; TP21.1 73.63,22.96 ; TP21.1 71.5,22.05 ; TP21.1 71.81,21.13 ; TP21.1 72.72,23.27 ; TP21.1 73.63,21.13 ; TP21.1 72.72,20.83 ; TP21.1 71.81,22.96 ; TP21.1 73.94,22.05 ; J9.2 129.21,53.88 ; J9.2 129.21,55.24 ; J9.2 128.84,53.33 ; J9.2 129.27,54.56 ; J9.2 128.84,55.79 ; J9.2 127.61,56.22 ; J9.2 126.38,55.79 ; J9.2 126.38,53.33 ; J9.2 126.01,53.88 ; J9.2 128.29,56.16 ; J9.2 125.95,54.56 ; J9.2 126.93,52.96 ; J9.2 126.01,55.24 ; J9.2 126.93,56.16 ; J9.2 128.29,52.96 ; J9.2 127.61,52.89 ; J13.3 133.92,64.13 ; J13.3 131.03,65.35 ; J13.3 132.69,63.69 ; J13.3 134.35,65.35 ; J13.3 132.69,67.02 ; J13.3 131.46,66.58 ; J13.3 133.92,66.58 ; J13.3 131.46,64.13 ; J13.2 128.84,64.13 ; J13.2 128.84,66.58 ; J13.2 127.61,67.02 ; J13.2 126.38,64.13 ; J13.2 129.27,65.35 ; J13.2 125.95,65.35 ; J13.2 127.61,63.69 ; J13.2 126.38,66.58 ; 55.98,17.55 TP14.1 ; TP14.1 57.81,15.72 ; TP14.1 58.12,16.64 ; TP14.1 57.81,17.55 ; TP14.1 56.9,17.86 ; TP14.1 55.68,16.64 ; TP14.1 55.98,15.72 ; TP14.1 56.9,15.42 ; J7.2 67.89,67.32 ; J7.2 66.23,65.66 ; J7.2 66.67,66.89 ; J7.2 69.12,64.43 ; J7.2 66.67,64.43 ; J7.2 69.56,65.66 ; J7.2 67.89,63.99 ; J7.2 69.12,66.89 ; J7.5 69.12,61.81 ; J7.5 66.67,59.35 ; J7.5 69.56,60.58 ; J7.5 66.67,61.81 ; J7.5 66.23,60.58 ; J7.5 67.89,62.24 ; J7.5 69.12,59.35 ; J13.5 129.27,60.27 ; J13.5 126.38,61.5 ; J13.5 127.61,58.61 ; J13.5 128.84,61.5 ; J13.5 128.84,59.05 ; J13.5 127.61,61.94 ; J13.5 125.95,60.27 ; J13.5 126.38,59.05 ; 39.42,2.29 TP18.1 ; TP18.1 39.42,5.49 ; TP18.1 37.82,3.89 ; TP18.1 40.6,2.7 ; TP18.1 38.24,2.7 ; TP18.1 40.6,5.07 ; TP18.1 41.02,3.89
  TOP w0.508: v3(132.94,7.19) 132.64,6.88 R11.1 132.11,7.19 v3(131.93,7.19) 131.62,6.88 C36.2 ; v4(97.56,54.31) 97.94,53.93 C99.1 ; v6(57.51,59.92) 57.73,59.69 C398.1 58.29,59.69 v6(58.52,59.92) ; v4(93.5,54.31) 93.32,54.13 93.04,54.48 92.66,54.13 v4(92.48,54.31) ; v4(91.47,60.4) 91.09,60.78 C87.1 ; R171.1 111.76,9.55 v3(111.73,9.53) ; v4(91.47,58.37) 91.16,58.06 C92.1 ; R170.1 111.02,8.2 v3(110.72,8.51) ; C98.1 97.82,59.13 v4(97.56,59.39) ; R127.1 124.44,8.36 v3(124.41,8.33) ; v3(132.94,8.2) 132.97,8.23 R13.1 ; v3(109.7,8.51) 110.01,8.2 C387.2 ; v1(91.03,54.1) 90.78,53.85 C90.1 ; C88.1 94.23,54.02 v4(94.52,54.31) ; C91.1 91.19,55.6 v4(91.47,55.32) ; v6(58.52,62.97) 58.29,63.2 C402.1 57.73,63.2 v6(57.51,62.97) ; v4(92.48,60.4) 92.41,60.48 C89.1 ; R14.1 133.12,9.4 v3(132.94,9.22) ; v3(111.73,8.51) 112.04,8.2 R172.1 ; C96.2 91.85,53.93 v4(91.47,54.31) ; v3(66.03,16.2) 66.18,16.05 SJP2.3 ; v3(122.38,7.31) 122.68,7.01 C166.2 123.09,7.01 v3(123.39,7.31) 123.7,7.01 R124.1 124.11,7.01 v3(124.41,7.31) 124.71,7.01 R125.1
  L2_GND w0.432: 48.01,65.05 JP2.1 ; JP2.1 48.88,65.34 ; JP2.1 49.17,66.22 ; JP2.1 47.13,67.1 ; JP2.1 46.84,66.22 ; JP2.1 48.01,67.39 ; JP2.1 48.88,67.1 ; JP2.1 47.13,65.34 ; TP21.1 72.72,23.27 ; TP21.1 73.63,22.96 ; TP21.1 73.94,22.05 ; TP21.1 71.5,22.05 ; TP21.1 71.81,22.96 ; TP21.1 72.72,20.83 ; TP21.1 73.63,21.13 ; TP21.1 71.81,21.13 ; J7.3 74.2,64.43 ; J7.3 71.75,64.43 ; J7.3 74.2,66.89 ; J7.3 72.97,63.99 ; J7.3 72.97,67.32 ; J7.3 71.75,66.89 ; J7.3 74.64,65.66 ; J7.3 71.31,65.66 ; J7.4 74.2,59.35 ; J7.4 71.31,60.58 ; J7.4 72.97,58.91 ; J7.4 71.75,61.81 ; J7.4 74.64,60.58 ; J7.4 71.75,59.35 ; J7.4 72.97,62.24 ; J7.4 74.2,61.81 ; 38.24,5.07 TP18.1 ; TP18.1 41.02,3.89 ; TP18.1 39.42,2.29 ; TP18.1 38.24,2.7 ; TP18.1 40.6,2.7 ; TP18.1 40.6,5.07 ; TP18.1 39.42,5.49 ; TP18.1 37.82,3.89 ; 40.94,63.35 JP3.2 ; JP3.2 42.11,62.18 ; JP3.2 42.99,62.47 ; JP3.2 42.11,64.52 ; JP3.2 41.24,64.22 ; JP3.2 41.24,62.47 ; JP3.2 43.28,63.35 ; JP3.2 42.99,64.22 ; 122.78,27.08 TP19.1 ; TP19.1 124.61,27.08 ; TP19.1 124.92,26.16 ; TP19.1 122.48,26.16 ; TP19.1 123.7,24.94 ; TP19.1 122.78,25.25 ; TP19.1 123.7,27.38 ; TP19.1 124.61,25.25 ; 127.61,58.61 J13.5 ; J13.5 125.95,60.27 ; J13.5 128.84,59.05 ; J13.5 126.38,59.05 ; J13.5 127.61,61.94 ; J13.5 128.84,61.5 ; J13.5 129.27,60.27 ; J13.5 126.38,61.5 ; MT1.1 20.15,66.38 ; MT1.1 18.67,66.92 ; MT1.1 20.15,63.42 ; MT1.1 18.67,62.88 ; MT1.1 17.19,63.42 ; MT1.1 16.65,64.9 ; MT1.1 17.19,66.38 ; MT1.1 20.69,64.9 ; J7.5 69.12,59.35 ; J7.5 66.67,59.35 ; J7.5 67.89,62.24 ; J7.5 67.89,58.91 ; J7.5 69.56,60.58 ; J7.5 66.23,60.58 ; J7.5 69.12,61.81 ; J7.5 66.67,61.81 ; 22.35,54.48 23.23,53.61 ; 22.35,54.48 22.35,55.65 ; 22.35,54.48 21.18,54.48 ; 22.35,54.48 23.23,55.36 ; 22.35,54.48 22.35,53.31 ; 22.35,54.48 23.52,54.48 ; 22.35,54.48 21.47,53.61 ; 22.35,54.48 21.47,55.36 ; J9.2 129.27,54.56 ; J9.2 125.95,54.56 ; J9.2 127.61,52.89 ; J9.2 127.61,56.22 ; J9.2 128.84,55.79 ; J9.2 126.38,53.33 ; J9.2 126.38,55.79 ; J9.2 128.84,53.33 ; 115.42,2.52 TP11.1 ; TP11.1 117.25,4.34 ; TP11.1 117.25,2.52 ; TP11.1 117.55,3.43 ; TP11.1 115.42,4.34 ; TP11.1 115.11,3.43 ; TP11.1 116.33,2.21 ; TP11.1 116.33,4.65 ; 131.03,49.48 J9.4 ; J9.4 132.69,51.14 ; J9.4 133.92,48.25 ; J9.4 133.92,50.71 ; J9.4 134.35,49.48 ; J9.4 131.46,50.71 ; J9.4 132.69,47.81 ; J9.4 131.46,48.25 ; 21.47,30.11 JP5.2 ; JP5.2 22.35,29.82 ; JP5.2 23.52,30.99 ; JP5.2 23.23,30.11 ; JP5.2 21.47,31.87 ; JP5.2 21.18,30.99 ; JP5.2 22.35,32.16 ; JP5.2 23.23,31.87 ; 104.12,23.52 TP6.1 ; TP6.1 103.81,22.61 ; TP6.1 105.94,21.69 ; TP6.1 104.12,21.69 ; TP6.1 105.03,21.39 ; TP6.1 106.25,22.61 ; TP6.1 105.94,23.52 ; TP6.1 105.03,23.83 ; J9.5 129.27,49.48 ; J9.5 126.38,50.71 ; J9.5 127.61,47.81 ; J9.5 125.95,49.48 ; J9.5 128.84,50.71 ; J9.5 128.84,48.25 ; J9.5 127.61,51.14 ; J9.5 126.38,48.25 ; J8.2 28.68,10.36 ; J8.2 31.01,8.03 ; J8.2 30.38,6.32 ; J8.2 26.97,9.73 ; J8.2 30.38,9.73 ; J8.2 28.68,5.69 ; J8.2 26.97,6.32 ; J8.2 26.34,8.03 ; TP14.1 57.81,15.72 ; TP14.1 56.9,15.42 ; TP14.1 55.98,17.55 ; TP14.1 56.9,17.86 ; TP14.1 58.12,16.64 ; TP14.1 57.81,17.55 ; TP14.1 55.68,16.64 ; TP14.1 55.98,15.72 ; 31.93,0.89 J8.3 ; J8.3 31.93,5.56 ; J8.3 33.63,4.93 ; J8.3 30.22,1.52 ; J8.3 33.63,1.52 ; J8.3 34.27,3.23 ; J8.3 29.59,3.23 ; J8.3 30.22,4.93 ; JP1.3 99.94,25.92 ; JP1.3 98.18,27.67 ; JP1.3 99.94,27.67 ; JP1.3 99.06,25.63 ; JP1.3 97.89,26.8 ; JP1.3 99.06,27.97 ; JP1.3 100.23,26.8 ; JP1.3 98.18,25.92 ; J7.2 67.89,67.32 ; J7.2 66.67,66.89 ; J7.2 67.89,63.99 ; J7.2 66.67,64.43 ; J7.2 66.23,65.66 ; J7.2 69.56,65.66 ; J7.2 69.12,66.89 ; J7.2 69.12,64.43 ; 131.03,65.35 J13.3 ; J13.3 131.46,66.58 ; J13.3 131.46,64.13 ; J13.3 132.69,63.69 ; J13.3 132.69,67.02 ; J13.3 133.92,66.58 ; J13.3 134.35,65.35 ; J13.3 133.92,64.13 ; 17.78,15.76 MT2.1 ; MT2.1 16.3,16.3 ; MT2.1 19.26,16.3 ; MT2.1 16.3,19.26 ; MT2.1 17.78,19.8 ; MT2.1 19.8,17.78 ; MT2.1 19.26,19.26 ; MT2.1 15.76,17.78 ; 125.95,65.35 J13.2 ; J13.2 126.38,66.58 ; J13.2 129.27,65.35 ; J13.2 127.61,63.69 ; J13.2 128.84,66.58 ; J13.2 126.38,64.13 ; J13.2 128.84,64.13 ; J13.2 127.61,67.02 ; 131.46,59.05 J13.4 ; J13.4 131.03,60.27 ; J13.4 131.46,61.5 ; J13.4 133.92,59.05 ; J13.4 132.69,61.94 ; J13.4 133.92,61.5 ; J13.4 134.35,60.27 ; J13.4 132.69,58.61 ; J9.3 133.92,53.33 ; J9.3 132.69,52.89 ; J9.3 134.35,54.56 ; J9.3 131.03,54.56 ; J9.3 133.92,55.79 ; J9.3 131.46,55.79 ; J9.3 132.69,56.22 ; J9.3 131.46,53.33
  L3_PWR w0.432: J9.2 128.84,55.79 ; J9.2 128.84,53.33 ; J9.2 126.38,53.33 ; J9.2 127.61,52.89 ; J9.2 126.38,55.79 ; J9.2 129.27,54.56 ; J9.2 127.61,56.22 ; J9.2 125.95,54.56 ; 131.46,64.13 J13.3 ; J13.3 132.69,67.02 ; J13.3 131.03,65.35 ; J13.3 133.92,66.58 ; J13.3 131.46,66.58 ; J13.3 133.92,64.13 ; J13.3 134.35,65.35 ; J13.3 132.69,63.69 ; 131.03,49.48 J9.4 ; J9.4 133.92,48.25 ; J9.4 133.92,50.71 ; J9.4 132.69,51.14 ; J9.4 131.46,48.25 ; J9.4 131.46,50.71 ; J9.4 132.69,47.81 ; J9.4 134.35,49.48 ; JP2.1 48.01,67.39 ; JP2.1 48.88,67.1 ; JP2.1 47.13,67.1 ; JP2.1 48.49,67.36 ; 126.38,61.5 J13.5 ; J13.5 127.61,58.61 ; J13.5 125.95,60.27 ; J13.5 127.61,61.94 ; J13.5 126.38,59.05 ; J13.5 129.27,60.27 ; J13.5 128.84,61.5 ; J13.5 128.84,59.05 ; J9.5 128.84,50.71 ; J9.5 127.61,47.81 ; J9.5 128.84,48.25 ; J9.5 126.38,50.71 ; J9.5 126.38,48.25 ; J9.5 125.95,49.48 ; J9.5 127.61,51.14 ; J9.5 129.27,49.48 ; 21.18,54.48 22.35,54.48 ; 22.35,54.48 21.47,53.61 ; 22.35,54.48 22.35,53.31 ; 22.35,54.48 22.35,55.65 ; 22.35,54.48 21.47,55.36 ; 22.35,54.48 23.23,53.61 ; 22.35,54.48 23.52,54.48 ; 22.35,54.48 23.23,55.36 ; J7.2 67.89,67.32 ; J7.2 69.12,66.89 ; J7.2 69.56,65.66 ; J7.2 69.12,64.43 ; J7.2 66.67,66.89 ; J7.4 72.97,62.24 ; J7.4 74.2,59.35 ; J7.4 71.75,61.81 ; J7.4 74.2,61.81 ; J7.4 74.64,60.58 ; MT2.1 19.8,17.78 ; MT2.1 19.26,16.3 ; MT2.1 16.3,19.26 ; MT2.1 15.76,17.78 ; MT2.1 17.78,19.8 ; MT2.1 17.78,15.76 ; MT2.1 19.26,19.26 ; MT2.1 16.3,16.3 ; J9.3 132.69,56.22 ; J9.3 133.92,53.33 ; J9.3 134.35,54.56 ; J9.3 131.46,55.79 ; J9.3 131.03,54.56 ; J9.3 132.69,52.89 ; J9.3 131.46,53.33 ; J9.3 133.92,55.79 ; 18.67,62.88 MT1.1 ; MT1.1 16.65,64.9 ; MT1.1 20.15,63.42 ; MT1.1 20.15,66.38 ; MT1.1 20.69,64.9 ; MT1.1 18.67,66.92 ; MT1.1 17.19,66.38 ; MT1.1 17.19,63.42 ; 71.5,22.05 TP21.1 ; TP21.1 71.81,22.96 ; TP21.1 72.72,20.83 ; TP21.1 73.94,22.05 ; TP21.1 73.63,21.13 ; TP21.1 71.81,21.13 ; TP21.1 72.72,23.27 ; J13.2 128.84,66.58 ; J13.2 126.38,64.13 ; J13.2 127.61,63.69 ; J13.2 125.95,65.35 ; J13.2 126.38,66.58 ; J13.2 127.61,67.02 ; J13.2 128.84,64.13 ; J13.2 129.27,65.35 ; 21.47,30.11 JP5.2 ; JP5.2 23.23,30.11 ; JP5.2 21.18,30.99 ; JP5.2 22.35,29.82 ; JP5.2 21.47,31.87 ; JP5.2 23.23,31.87 ; JP5.2 22.35,32.16 ; JP5.2 23.52,30.99 ; J8.2 28.68,10.36 ; J8.2 28.68,5.69 ; J8.2 26.34,8.03 ; J8.2 26.97,6.32 ; J8.2 26.97,9.73 ; 132.69,58.61 J13.4 ; J13.4 131.03,60.27 ; J13.4 134.35,60.27 ; J13.4 131.46,59.05 ; J13.4 131.46,61.5 ; J13.4 133.92,59.05 ; J13.4 132.69,61.94 ; J13.4 133.92,61.5 ; 71.31,65.66 J7.3 ; J7.3 74.2,64.43 ; J7.3 72.97,63.99 ; J7.3 71.75,64.43 ; J7.3 72.97,67.32 ; J7.3 74.64,65.66 ; J7.3 74.2,66.89 ; J7.3 71.75,66.89 ; TP19.1 123.7,27.38 ; TP19.1 124.92,26.16 ; TP19.1 124.61,27.08 ; TP19.1 122.78,25.25 ; TP19.1 122.48,26.16 ; TP19.1 123.7,24.94 ; TP19.1 122.78,27.08 ; TP19.1 124.61,25.25 ; J8.3 32.86,1.01 ; J8.3 30.22,1.52 ; J8.3 31.93,0.89 ; J8.3 30.99,1.01
  L4_SIG w0.432: 21.18,54.48 22.35,54.48 ; 22.35,54.48 23.23,55.36 ; 22.35,54.48 23.52,54.48 ; 22.35,54.48 21.47,53.61 ; 22.35,54.48 23.23,53.61 ; 22.35,54.48 22.35,53.31 ; 22.35,54.48 22.35,55.65 ; 22.35,54.48 21.47,55.36 ; 42.11,62.18 JP3.2 ; JP3.2 42.99,62.47 ; JP3.2 41.24,64.22 ; JP3.2 41.24,62.47 ; JP3.2 42.99,64.22 ; JP3.2 43.28,63.35 ; JP3.2 42.11,64.52 ; TP19.1 123.7,27.38 ; TP19.1 124.61,27.08 ; TP19.1 122.48,26.16 ; TP19.1 123.7,24.94 ; TP19.1 122.78,27.08 ; TP19.1 124.61,25.25 ; TP19.1 124.92,26.16 ; TP19.1 122.78,25.25 ; 22.35,29.82 JP5.2 ; JP5.2 23.23,31.87 ; JP5.2 21.47,31.87 ; JP5.2 23.52,30.99 ; JP5.2 23.23,30.11 ; JP5.2 21.18,30.99 ; JP5.2 22.35,32.16 ; JP5.2 21.47,30.11 ; J7.4 74.64,60.58 ; J7.4 71.75,61.81 ; J7.4 74.2,59.35 ; J7.4 72.97,58.91 ; J7.4 74.2,61.81 ; J7.4 72.97,62.24 ; J7.4 71.75,59.35 ; J7.4 71.31,60.58 ; MT2.1 19.26,19.26 ; MT2.1 17.78,15.76 ; MT2.1 15.76,17.78 ; MT2.1 16.3,19.26 ; MT2.1 16.3,16.3 ; MT2.1 19.26,16.3 ; MT2.1 19.8,17.78 ; MT2.1 17.78,19.8 ; J13.2 127.61,67.02 ; J13.2 125.95,65.35 ; J13.2 129.27,65.35 ; J13.2 126.38,64.13 ; J13.2 126.38,66.58 ; J13.2 128.84,66.58 ; J13.2 127.61,63.69 ; J13.2 128.84,64.13 ; 127.61,52.89 J9.2 ; J9.2 129.27,54.56 ; J9.2 128.84,53.33 ; J9.2 128.84,55.79 ; J9.2 126.38,53.33 ; J9.2 125.95,54.56 ; J9.2 126.38,55.79 ; J9.2 127.61,56.22 ; J8.3 33.63,4.93 ; J8.3 34.27,3.23 ; J8.3 31.93,5.56 ; J8.3 30.22,1.52 ; J8.3 29.59,3.23 ; J8.3 33.63,1.52 ; J8.3 31.93,0.89 ; J8.3 30.22,4.93 ; TP18.1 40.6,5.07 ; TP18.1 39.42,2.29 ; TP18.1 39.42,5.49 ; TP18.1 41.02,3.89 ; TP18.1 38.24,2.7 ; TP18.1 38.24,5.07 ; TP18.1 37.82,3.89 ; TP18.1 40.6,2.7 ; 46.84,66.22 JP2.1 ; JP2.1 48.88,67.1 ; JP2.1 48.88,65.34 ; JP2.1 48.01,67.39 ; JP2.1 48.01,65.05 ; JP2.1 49.17,66.22 ; JP2.1 47.13,67.1 ; JP2.1 47.13,65.34 ; TP6.1 105.94,23.52 ; TP6.1 105.03,21.39 ; TP6.1 106.25,22.61 ; TP6.1 105.03,23.83 ; TP6.1 103.81,22.61 ; TP6.1 104.12,23.52 ; TP6.1 104.12,21.69 ; TP6.1 105.94,21.69 ; MT1.1 20.15,63.42 ; MT1.1 17.19,63.42 ; MT1.1 17.19,66.38 ; MT1.1 20.69,64.9 ; MT1.1 20.15,66.38 ; MT1.1 16.65,64.9 ; MT1.1 18.67,62.88 ; MT1.1 18.67,66.92 ; J9.5 127.61,51.14 ; J9.5 128.84,48.25 ; J9.5 128.84,50.71 ; J9.5 127.61,47.81 ; J9.5 126.38,50.71 ; J9.5 125.95,49.48 ; J9.5 126.38,48.25 ; J9.5 129.27,49.48 ; 66.23,60.58 J7.5 ; J7.5 66.67,61.81 ; J7.5 66.67,59.35 ; J7.5 69.12,59.35 ; J7.5 69.56,60.58 ; J7.5 67.89,58.91 ; J7.5 69.12,61.81 ; J7.5 67.89,62.24 ; 131.46,53.33 J9.3 ; J9.3 132.69,52.89 ; J9.3 133.92,55.79 ; J9.3 131.03,54.56 ; J9.3 132.69,56.22 ; J9.3 131.46,55.79 ; J9.3 134.35,54.56 ; J9.3 133.92,53.33 ; J13.3 134.35,65.35 ; J13.3 131.03,65.35 ; J13.3 131.46,64.13 ; J13.3 132.69,63.69 ; J13.3 133.92,66.58 ; J13.3 132.69,67.02 ; J13.3 131.46,66.58 ; J13.3 133.92,64.13 ; J9.4 134.35,49.48 ; J9.4 133.92,48.25 ; J9.4 132.69,47.81 ; J9.4 131.03,49.48 ; J9.4 132.69,51.14 ; J9.4 131.46,50.71 ; J9.4 131.46,48.25 ; J9.4 133.92,50.71 ; TP21.1 72.72,23.27 ; TP21.1 73.94,22.05 ; TP21.1 73.63,21.13 ; TP21.1 71.5,22.05 ; TP21.1 73.63,22.96 ; TP21.1 71.81,22.96 ; TP21.1 71.81,21.13 ; TP21.1 72.72,20.83 ; J7.2 69.12,64.43 ; J7.2 69.12,66.89 ; J7.2 66.67,64.43 ; J7.2 66.67,66.89 ; J7.2 67.89,67.32 ; J7.2 66.23,65.66 ; J7.2 69.56,65.66 ; J7.2 67.89,63.99 ; TP11.1 117.25,2.52 ; TP11.1 115.42,4.34 ; TP11.1 115.11,3.43 ; TP11.1 115.42,2.52 ; TP11.1 116.33,2.21 ; TP11.1 117.55,3.43 ; TP11.1 117.25,4.34 ; TP11.1 116.33,4.65 ; 55.68,16.64 TP14.1 ; TP14.1 57.81,15.72 ; TP14.1 55.98,15.72 ; TP14.1 58.12,16.64 ; 28.68,5.69 J8.2 ; J8.2 28.68,10.36 ; J8.2 26.97,6.32 ; J8.2 26.97,9.73 ; J8.2 30.38,9.73 ; J8.2 26.34,8.03 ; J8.2 30.38,6.32 ; J8.2 31.01,8.03 ; 71.75,66.89 J7.3 ; J7.3 71.75,64.43 ; J7.3 72.97,67.32 ; J7.3 74.2,66.89 ; J7.3 74.64,65.66 ; J7.3 71.31,65.66 ; J7.3 72.97,63.99 ; J7.3 74.2,64.43 ; 131.03,60.27 J13.4 ; J13.4 131.46,59.05 ; J13.4 132.69,58.61 ; J13.4 132.69,61.94 ; J13.4 133.92,61.5 ; J13.4 133.92,59.05 ; J13.4 131.46,61.5 ; J13.4 134.35,60.27 ; JP1.3 99.06,27.97 ; JP1.3 99.94,25.92 ; JP1.3 99.06,25.63 ; JP1.3 97.89,26.8 ; JP1.3 98.18,25.92 ; JP1.3 98.18,27.67 ; JP1.3 100.23,26.8 ; JP1.3 99.94,27.67 ; 126.38,59.05 J13.5 ; J13.5 128.84,61.5 ; J13.5 127.61,61.94 ; J13.5 127.61,58.61 ; J13.5 129.27,60.27 ; J13.5 128.84,59.05 ; J13.5 126.38,61.5 ; J13.5 125.95,60.27
  L5_GND w0.432: MT2.1 19.8,17.78 ; MT2.1 16.3,16.3 ; MT2.1 16.3,19.26 ; MT2.1 15.76,17.78 ; MT2.1 19.26,19.26 ; MT2.1 19.26,16.3 ; MT2.1 17.78,19.8 ; MT2.1 17.78,15.76 ; TP19.1 124.61,27.08 ; TP19.1 122.48,26.16 ; TP19.1 123.7,24.94 ; TP19.1 123.7,27.38 ; TP19.1 124.61,25.25 ; TP19.1 122.78,25.25 ; TP19.1 122.78,27.08 ; TP19.1 124.92,26.16 ; J8.2 28.68,10.36 ; J8.2 28.68,5.69 ; J8.2 26.97,6.32 ; J8.2 30.38,6.32 ; J8.2 30.38,9.73 ; J8.2 31.01,8.03 ; J8.2 26.97,9.73 ; J8.2 26.34,8.03 ; MT1.1 18.67,66.92 ; MT1.1 18.67,62.88 ; MT1.1 20.15,63.42 ; MT1.1 20.69,64.9 ; MT1.1 20.15,66.38 ; MT1.1 17.19,66.38 ; MT1.1 17.19,63.42 ; MT1.1 16.65,64.9 ; 132.69,58.61 J13.4 ; J13.4 133.92,59.05 ; J13.4 131.46,59.05 ; J13.4 134.35,60.27 ; J13.4 133.92,61.5 ; J13.4 131.46,61.5 ; J13.4 132.69,61.94 ; J13.4 131.03,60.27 ; 97.89,26.8 JP1.3 ; JP1.3 98.18,25.92 ; JP1.3 99.06,27.97 ; JP1.3 99.94,27.67 ; JP1.3 99.06,25.63 ; JP1.3 98.18,27.67 ; JP1.3 100.23,26.8 ; JP1.3 99.94,25.92 ; J7.2 67.89,67.32 ; J7.2 66.23,65.66 ; J7.2 69.12,64.43 ; J7.2 66.67,64.43 ; J7.2 69.56,65.66 ; J7.2 67.89,63.99 ; J7.2 66.67,66.89 ; J7.2 69.12,66.89 ; 127.61,63.69 J13.2 ; J13.2 127.61,67.02 ; J13.2 129.27,65.35 ; J13.2 126.38,66.58 ; J13.2 126.38,64.13 ; J13.2 128.84,66.58 ; J13.2 128.84,64.13 ; J13.2 125.95,65.35 ; J8.3 33.63,1.52 ; J8.3 30.22,1.52 ; J8.3 31.93,0.89 ; J8.3 33.63,4.93 ; J8.3 34.27,3.23 ; J8.3 30.22,4.93 ; J8.3 29.59,3.23 ; J8.3 31.93,5.56 ; J9.4 133.92,48.25 ; J9.4 131.46,48.25 ; J9.4 132.69,47.81 ; J9.4 134.35,49.48 ; J9.4 132.69,51.14 ; J9.4 133.92,50.71 ; J9.4 131.03,49.48 ; J9.4 131.46,50.71 ; J13.5 128.84,59.05 ; J13.5 128.84,61.5 ; J13.5 125.95,60.27 ; J13.5 127.61,58.61 ; J13.5 126.38,61.5 ; J13.5 126.38,59.05 ; J13.5 127.61,61.94 ; J13.5 129.27,60.27 ; 66.67,59.35 J7.5 ; J7.5 66.67,61.81 ; J7.5 67.89,58.91 ; J7.5 69.12,61.81 ; J7.5 66.23,60.58 ; J7.5 69.12,59.35 ; J7.5 67.89,62.24 ; J7.5 69.56,60.58 ; 104.12,21.69 TP6.1 ; TP6.1 106.25,22.61 ; TP6.1 104.12,23.52 ; TP6.1 105.03,23.83 ; TP6.1 105.03,21.39 ; TP6.1 103.81,22.61 ; TP6.1 105.94,23.52 ; TP6.1 105.94,21.69 ; 21.47,30.11 JP5.2 ; JP5.2 21.18,30.99 ; JP5.2 23.52,30.99 ; JP5.2 23.23,30.11 ; JP5.2 21.47,31.87 ; JP5.2 22.35,32.16 ; JP5.2 22.35,29.82 ; JP5.2 23.23,31.87 ; J9.3 134.35,54.56 ; J9.3 131.03,54.56 ; J9.3 131.46,53.33 ; J9.3 131.46,55.79 ; J9.3 133.92,55.79 ; J9.3 132.69,52.89 ; J9.3 132.69,56.22 ; J9.3 133.92,53.33 ; J13.3 133.92,66.58 ; J13.3 131.03,65.35 ; J13.3 132.69,67.02 ; J13.3 134.35,65.35 ; J13.3 131.46,64.13 ; J13.3 131.46,66.58 ; J13.3 132.69,63.69 ; J13.3 133.92,64.13 ; 72.97,63.99 J7.3 ; J7.3 71.75,64.43 ; J7.3 71.75,66.89 ; J7.3 71.31,65.66 ; J7.3 74.64,65.66 ; J7.3 72.97,67.32 ; J7.3 74.2,64.43 ; J7.3 74.2,66.89 ; JP2.1 48.88,67.1 ; JP2.1 46.84,66.22 ; JP2.1 48.01,65.05 ; JP2.1 49.17,66.22 ; JP2.1 48.88,65.34 ; JP2.1 48.01,67.39 ; JP2.1 47.13,67.1 ; JP2.1 47.13,65.34 ; 116.33,2.21 TP11.1 ; TP11.1 115.42,2.52 ; TP11.1 117.25,2.52 ; TP11.1 116.33,4.65 ; TP11.1 117.55,3.43 ; TP11.1 115.11,3.43 ; TP11.1 115.42,4.34 ; TP11.1 117.25,4.34 ; 22.35,54.48 23.52,54.48 ; 22.35,54.48 21.47,53.61 ; 22.35,54.48 22.35,55.65 ; 22.35,54.48 23.23,55.36 ; 22.35,54.48 21.18,54.48 ; 22.35,54.48 21.47,55.36 ; 22.35,54.48 22.35,53.31 ; 22.35,54.48 23.23,53.61 ; 71.5,22.05 TP21.1 ; TP21.1 73.94,22.05 ; TP21.1 72.72,23.27 ; TP21.1 71.81,21.13 ; TP21.1 73.63,22.96 ; TP21.1 73.63,21.13 ; TP21.1 71.81,22.96 ; TP21.1 72.72,20.83 ; 126.38,50.71 J9.5 ; J9.5 126.38,48.25 ; J9.5 125.95,49.48 ; J9.5 127.61,51.14 ; J9.5 128.84,48.25 ; J9.5 129.27,49.48 ; J9.5 127.61,47.81 ; J9.5 128.84,50.71 ; TP18.1 41.02,3.89 ; TP18.1 38.24,2.7 ; TP18.1 40.6,2.7 ; TP18.1 40.6,5.07 ; TP18.1 38.24,5.07 ; TP18.1 37.82,3.89 ; TP18.1 39.42,2.29 ; TP18.1 39.42,5.49 ; J7.4 74.2,59.35 ; J7.4 71.75,59.35 ; J7.4 74.2,61.81 ; J7.4 71.75,61.81 ; J7.4 71.31,60.58 ; J7.4 74.64,60.58 ; J7.4 72.97,58.91 ; J7.4 72.97,62.24 ; 55.98,15.72 TP14.1 ; TP14.1 57.81,17.55 ; TP14.1 55.68,16.64 ; TP14.1 57.81,15.72 ; TP14.1 56.9,17.86 ; TP14.1 56.9,15.42 ; TP14.1 55.98,17.55 ; TP14.1 58.12,16.64 ; 41.24,64.22 JP3.2 ; JP3.2 42.11,64.52 ; JP3.2 40.94,63.35 ; JP3.2 42.11,62.18 ; JP3.2 42.99,64.22 ; JP3.2 42.99,62.47 ; JP3.2 43.28,63.35 ; JP3.2 41.24,62.47 ; J9.2 129.27,54.56 ; J9.2 125.95,54.56 ; J9.2 128.84,55.79 ; J9.2 127.61,52.89 ; J9.2 128.84,53.33 ; J9.2 126.38,53.33 ; J9.2 126.38,55.79 ; J9.2 127.61,56.22
  L6_PWR w0.432: 115.42,2.52 TP11.1 ; TP11.1 117.55,3.43 ; TP11.1 116.33,4.65 ; TP11.1 115.11,3.43 ; TP11.1 115.42,4.34 ; TP11.1 117.25,2.52 ; TP11.1 116.33,2.21 ; TP11.1 117.25,4.34 ; 46.84,66.22 JP2.1 ; JP2.1 47.13,67.1 ; JP2.1 48.88,67.1 ; JP2.1 47.13,65.34 ; JP2.1 49.17,66.22 ; JP2.1 48.01,65.05 ; JP2.1 48.88,65.34 ; JP2.1 48.01,67.39 ; 71.75,64.43 J7.3 ; J7.3 71.31,65.66 ; J7.3 74.64,65.66 ; J7.3 72.97,67.32 ; J7.3 71.75,66.89 ; J7.3 74.2,66.89 ; J7.3 72.97,63.99 ; J7.3 74.2,64.43 ; 67.89,63.99 J7.2 ; J7.2 69.12,64.43 ; J7.2 67.89,67.32 ; J7.2 69.12,66.89 ; J7.2 66.67,64.43 ; J7.2 66.67,66.89 ; J7.2 69.56,65.66 ; J7.2 66.23,65.66 ; 131.46,66.58 J13.3 ; J13.3 134.35,65.35 ; J13.3 132.69,67.02 ; J13.3 131.03,65.35 ; J13.3 133.92,64.13 ; J13.3 132.69,63.69 ; J13.3 131.46,64.13 ; J13.3 133.92,66.58 ; J8.3 33.63,1.52 ; J8.3 30.22,4.93 ; J8.3 34.27,3.23 ; J8.3 29.59,3.23 ; J8.3 30.22,1.52 ; J8.3 33.63,4.93 ; J8.3 31.93,0.89 ; 17.19,63.42 MT1.1 ; MT1.1 18.67,66.92 ; MT1.1 20.15,63.42 ; MT1.1 17.19,66.38 ; MT1.1 16.65,64.9 ; MT1.1 20.69,64.9 ; MT1.1 20.15,66.38 ; MT1.1 18.67,62.88 ; 71.75,59.35 J7.4 ; J7.4 74.2,61.81 ; J7.4 71.75,61.81 ; J7.4 72.97,58.91 ; J7.4 72.97,62.24 ; J7.4 74.2,59.35 ; J7.4 74.64,60.58 ; J7.4 71.31,60.58 ; J7.5 67.89,62.24 ; J7.5 66.67,59.35 ; J7.5 69.12,59.35 ; J7.5 66.67,61.81 ; J7.5 69.56,60.58 ; J7.5 66.23,60.58 ; J7.5 69.12,61.81 ; J7.5 67.89,58.91 ; 22.35,54.48 23.23,55.36 ; 22.35,54.48 23.52,54.48 ; 22.35,54.48 22.35,55.65 ; 22.35,54.48 23.23,53.61 ; 22.35,54.48 21.18,54.48 ; 22.35,54.48 21.47,55.36 ; 22.35,54.48 22.35,53.31 ; 22.35,54.48 21.47,53.61 ; 39.42,2.29 TP18.1 ; TP18.1 40.6,2.7 ; TP18.1 38.24,5.07 ; TP18.1 41.02,3.89 ; TP18.1 37.82,3.89 ; TP18.1 38.24,2.7 ; TP18.1 40.6,5.07 ; JP3.2 43.28,63.35 ; JP3.2 42.11,64.52 ; JP3.2 41.24,62.47 ; JP3.2 42.99,62.47 ; JP3.2 40.94,63.35 ; JP3.2 42.11,62.18 ; JP3.2 41.24,64.22 ; JP3.2 42.99,64.22 ; 126.38,66.58 J13.2 ; J13.2 129.27,65.35 ; J13.2 127.61,67.02 ; J13.2 128.84,66.58 ; J13.2 128.84,64.13 ; J13.4 133.92,59.05 ; J13.4 132.69,61.94 ; J13.4 134.35,60.27 ; J13.4 133.92,61.5 ; J13.4 131.46,61.5 ; 16.97,15.85 MT2.1 ; MT2.1 15.76,17.78 ; MT2.1 16.3,19.26 ; MT2.1 16.3,16.3 ; 105.03,21.39 TP6.1 ; TP6.1 104.12,23.52 ; TP6.1 105.03,23.83 ; TP6.1 105.94,23.52 ; TP6.1 104.12,21.69 ; TP6.1 105.94,21.69 ; TP6.1 106.25,22.61 ; 55.98,15.72 TP14.1 ; TP14.1 57.81,15.72 ; TP14.1 56.39,15.45 ; TP14.1 56.9,15.42
  L7_GND w0.432: 98.18,25.92 JP1.3 ; JP1.3 98.18,27.67 ; JP1.3 97.89,26.8 ; JP1.3 99.94,27.67 ; JP1.3 99.94,25.92 ; JP1.3 100.23,26.8 ; JP1.3 99.06,25.63 ; JP1.3 99.06,27.97 ; J7.4 74.2,59.35 ; J7.4 71.31,60.58 ; J7.4 71.75,59.35 ; J7.4 74.64,60.58 ; J7.4 71.75,61.81 ; J7.4 74.2,61.81 ; J7.4 72.97,62.24 ; J7.4 72.97,58.91 ; 71.75,64.43 J7.3 ; J7.3 72.97,63.99 ; J7.3 71.31,65.66 ; J7.3 74.2,66.89 ; J7.3 72.97,67.32 ; J7.3 74.2,64.43 ; J7.3 71.75,66.89 ; J7.3 74.64,65.66 ; 21.18,54.48 22.35,54.48 ; 22.35,54.48 22.35,53.31 ; 22.35,54.48 21.47,55.36 ; 22.35,54.48 21.47,53.61 ; 22.35,54.48 22.35,55.65 ; 22.35,54.48 23.52,54.48 ; 22.35,54.48 23.23,55.36 ; 22.35,54.48 23.23,53.61 ; TP6.1 106.25,22.61 ; TP6.1 105.94,21.69 ; TP6.1 103.81,22.61 ; TP6.1 105.94,23.52 ; TP6.1 105.03,23.83 ; TP6.1 104.12,21.69 ; TP6.1 105.03,21.39 ; TP6.1 104.12,23.52 ; TP11.1 117.25,4.34 ; TP11.1 116.33,4.65 ; TP11.1 115.42,4.34 ; TP11.1 115.42,2.52 ; TP11.1 117.25,2.52 ; TP11.1 116.33,2.21 ; TP11.1 117.55,3.43 ; TP11.1 115.11,3.43 ; J9.2 129.27,54.56 ; J9.2 127.61,52.89 ; J9.2 128.84,55.79 ; J9.2 125.95,54.56 ; J9.2 127.61,56.22 ; J9.2 126.38,53.33 ; J9.2 126.38,55.79 ; J9.2 128.84,53.33 ; 122.78,25.25 TP19.1 ; TP19.1 122.78,27.08 ; TP19.1 122.48,26.16 ; TP19.1 124.61,25.25 ; TP19.1 124.61,27.08 ; TP19.1 124.92,26.16 ; TP19.1 123.7,27.38 ; TP19.1 123.7,24.94 ; J8.3 33.63,1.52 ; J8.3 30.22,1.52 ; J8.3 31.93,5.56 ; J8.3 34.27,3.23 ; J8.3 30.22,4.93 ; J8.3 33.63,4.93 ; J8.3 29.59,3.23 ; J8.3 31.93,0.89 ; 26.97,6.32 J8.2 ; J8.2 30.38,9.73 ; J8.2 28.68,10.36 ; J8.2 31.01,8.03 ; J8.2 26.97,9.73 ; J8.2 30.38,6.32 ; J8.2 28.68,5.69 ; J8.2 26.34,8.03 ; 55.98,17.55 TP14.1 ; TP14.1 55.68,16.64 ; TP14.1 55.98,15.72 ; TP14.1 57.81,17.55 ; TP14.1 58.12,16.64 ; TP14.1 57.81,15.72 ; TP14.1 56.9,17.86 ; TP14.1 56.9,15.42 ; 131.03,60.27 J13.4 ; J13.4 132.69,61.94 ; J13.4 131.46,61.5 ; J13.4 133.92,59.05 ; J13.4 131.46,59.05 ; J13.4 134.35,60.27 ; J13.4 132.69,58.61 ; J13.4 133.92,61.5 ; 67.89,63.99 J7.2 ; J7.2 66.23,65.66 ; J7.2 66.67,66.89 ; J7.2 69.12,66.89 ; J7.2 69.12,64.43 ; J7.2 69.56,65.66 ; J7.2 66.67,64.43 ; J7.2 67.89,67.32 ; MT1.1 20.15,63.42 ; MT1.1 16.65,64.9 ; MT1.1 17.19,63.42 ; MT1.1 20.69,64.9 ; MT1.1 20.15,66.38 ; MT1.1 18.67,66.92 ; MT1.1 17.19,66.38 ; MT1.1 18.67,62.88 ; 16.3,19.26 MT2.1 ; MT2.1 19.8,17.78 ; MT2.1 15.76,17.78 ; MT2.1 17.78,15.76 ; MT2.1 17.78,19.8 ; MT2.1 19.26,19.26 ; MT2.1 19.26,16.3 ; MT2.1 16.3,16.3 ; 131.46,55.79 J9.3 ; J9.3 131.03,54.56 ; J9.3 133.92,53.33 ; J9.3 132.69,52.89 ; J9.3 131.46,53.33 ; J9.3 133.92,55.79 ; J9.3 132.69,56.22 ; J9.3 134.35,54.56 ; 71.81,22.96 TP21.1 ; TP21.1 73.63,21.13 ; TP21.1 72.72,23.27 ; TP21.1 73.94,22.05 ; TP21.1 71.81,21.13 ; TP21.1 73.63,22.96 ; TP21.1 71.5,22.05 ; TP21.1 72.72,20.83 ; J13.5 127.61,61.94 ; J13.5 128.84,61.5 ; J13.5 127.61,58.61 ; J13.5 126.38,59.05 ; J13.5 125.95,60.27 ; J13.5 128.84,59.05 ; J13.5 129.27,60.27 ; J13.5 126.38,61.5 ; JP2.1 49.17,66.22 ; JP2.1 48.88,67.1 ; JP2.1 47.13,67.1 ; JP2.1 48.88,65.34 ; JP2.1 48.01,67.39 ; JP2.1 47.13,65.34 ; JP2.1 48.01,65.05 ; JP2.1 46.84,66.22 ; 131.46,48.25 J9.4 ; J9.4 131.46,50.71 ; J9.4 133.92,50.71 ; J9.4 131.03,49.48 ; J9.4 132.69,51.14 ; J9.4 133.92,48.25 ; J9.4 132.69,47.81 ; J9.4 134.35,49.48 ; 126.38,64.13 J13.2 ; J13.2 126.38,66.58 ; J13.2 127.61,67.02 ; J13.2 128.84,66.58 ; J13.2 125.95,65.35 ; J13.2 129.27,65.35 ; J13.2 127.61,63.69 ; J13.2 128.84,64.13 ; JP3.2 42.99,64.22 ; JP3.2 41.24,62.47 ; JP3.2 43.28,63.35 ; JP3.2 41.24,64.22 ; JP3.2 42.11,64.52 ; JP3.2 42.11,62.18 ; JP3.2 42.99,62.47 ; JP3.2 40.94,63.35 ; TP18.1 40.6,2.7 ; TP18.1 38.24,5.07 ; TP18.1 37.82,3.89 ; TP18.1 38.24,2.7 ; TP18.1 39.42,5.49 ; TP18.1 41.02,3.89 ; TP18.1 40.6,5.07 ; TP18.1 39.42,2.29 ; 131.03,65.35 J13.3 ; J13.3 133.92,64.13 ; J13.3 134.35,65.35 ; J13.3 131.46,64.13 ; J13.3 133.92,66.58 ; J13.3 132.69,63.69 ; J13.3 131.46,66.58 ; J13.3 132.69,67.02 ; 126.38,50.71 J9.5 ; J9.5 127.61,51.14 ; J9.5 125.95,49.48 ; J9.5 127.61,47.81 ; J9.5 129.27,49.48 ; J9.5 126.38,48.25 ; J9.5 128.84,50.71 ; J9.5 128.84,48.25 ; 21.47,31.87 JP5.2 ; JP5.2 22.35,32.16 ; JP5.2 23.23,31.87 ; JP5.2 22.35,29.82 ; JP5.2 21.18,30.99 ; JP5.2 21.47,30.11 ; JP5.2 23.23,30.11 ; JP5.2 23.52,30.99 ; 67.89,58.91 J7.5 ; J7.5 66.67,61.81 ; J7.5 69.12,59.35 ; J7.5 69.56,60.58 ; J7.5 67.89,62.24 ; J7.5 66.23,60.58 ; J7.5 66.67,59.35 ; J7.5 69.12,61.81
  BOTTOM w0.305: R64.2 89.6,49.69 v1(89.55,49.64) ; U10.13 59.26,60.19 v6(58.52,60.93) U10.41 v6(58.52,61.95) v6(59.54,62.97) ; J10.G14 v3(141.66,43.26) ; v6(56.49,62.97) 55.83,63.63 55.83,63.93 55.76,64 U10.31 ; U10.34 57.26,63.21 v6(57.51,62.97) ; v1(91.78,49.69) 91.73,49.74 R63.2 ; v3(123.39,8.33) 124.04,8.98 U12.7 v1(126.53,8.98) ; v6(59.54,61.95) 59.78,62.19 U10.4 ; v2(54.64,61.16) 54.66,61.19 U10.25 56.23,61.19 v6(56.49,60.93) ; R70.2 94.03,47.07 v1(94.08,47.12) ; v1(100.43,63.17) 100.08,63.17 99.85,63.4 v1(99.57,63.4) ; 46.23,40.06 46.28,40.01 C58.2 ; v1(102.75,63.17) 102.05,63.17 v1(102.03,63.14) 101.96,63.07 v1(101.19,63.07) ; 46.23,45.41 46.28,45.46 C60.2 ; v1(91.82,47.12) 91.87,47.07 R69.2 ; v3(66.03,17.21) U16.18 63.82,17.21 v1(63.8,17.19) ; v6(58.52,59.92) 58.76,59.68 U10.14 ; C86.1 100.63,63.02 C72.2 ; v1(113.95,10.17) U9.7 112.1,10.17 v3(111.73,10.54) ; v3(85.84,14.51) 85.89,14.56 U17.12 v1(85.89,16.54) ; U4.7 v1(136.62,8.85) ; v1(70.2,17.21) U16.8 v3(68.06,17.21) ; v6(59.54,60.93) 59.8,61.19 U10.6 ; v1(58.65,52.91) 58.62,52.93 R192.1 ; J10.D16 v3(145.38,40.81) ; v1(49.13,7.01) v1(49.61,7.01)
  BOTTOM w0.381: v3(149.1,53.39) 148.59,52.88 J10.B6 ; J10.B10 v3(149.15,48.31) ; J10.B10 148.56,47.75 v3(148.01,48.31) ; J10.B10 J10.B11 ; J10.J17 139.67,38.86 138.43,37.62 J10.K18 138.4,37.59 v3(137.82,38.18) ; v3(139.14,54.69) 139.7,54.13 J10.J5 ; 46.23,40.06 v3(46.19,40.11) ; v3(144.07,37.01) 143.51,37.57 J10.F18 ; J10.F2 143.51,57.94 v3(144.04,58.47) ; J10.B15 148.56,41.4 v3(148.01,41.96) ; J10.B2 v3(149.15,58.47) ; J10.D7 v3(146.66,50.95) ; J10.D3 v3(146.61,56.08) ; v3(144.07,56.11) 143.54,56.64 J10.F3 ; v3(145.34,38.28) 144.78,38.84 J10.E17 ; v1(10.49,10.62) 10.13,10.26 v1(10.13,10.11) ; v1(144.22,45.87) 144.73,46.48 J10.E11 ; v3(150.37,44.48) 149.86,43.97 J10.A13 ; v3(144.78,35.05) v3(145.49,34.34) ; J10.K9 138.38,49.02 v1(137.74,49.66) ; J10.G8 142.24,50.27 v3(142.85,49.66) ; J10.G20 v3(142.24,35.03) v3(141.58,34.37) ; v3(146.63,48.29) 146.1,47.75 J10.D10 ; v1(7.92,10.11) v1(9.37,10.11) ; J10.B14 v3(149.17,42.09) ; v3(147.32,35.05) 147.32,35.03 v3(147.99,34.35) ; v3(139.7,35.05) 139.7,34.9 v3(139.01,34.21) ; J10.K6 v1(137.9,53.37) ; J10.D2 v3(146.61,58.47) ; J10.B3 148.62,56.64 v3(149.1,56.16) ; v3(142.85,38.33) 142.32,38.86 J10.G17 v3(141.58,38.2) J10.H18 ; J10.E5 v3(145.72,53.16) J10.D6 ; v3(147.88,54.64) 147.35,54.1 J10.C5 ; J10.A12 v3(150.5,45.21) ; J10.H9 v3(140.41,49.58) J10.J8 ; J10.A16 v1(150.55,40.13)
  BOTTOM w0.432: MT1.1 20.28,66.51 ; MT1.1 18.67,62.69 ; MT1.1 18.67,67.11 ; MT1.1 20.28,63.28 ; MT1.1 16.46,64.9 ; MT1.1 17.06,66.51 ; MT1.1 17.06,63.28 ; MT1.1 20.88,64.9 ; TP21.1 73.63,21.13 ; TP21.1 71.81,22.96 ; TP21.1 71.5,22.05 ; TP21.1 72.72,23.27 ; TP21.1 72.72,20.83 ; TP21.1 71.81,21.13 ; TP21.1 73.94,22.05 ; TP21.1 73.63,22.96 ; 122.78,27.08 TP19.1 ; TP19.1 122.78,25.25 ; TP19.1 123.7,27.38 ; TP19.1 124.92,26.16 ; TP19.1 122.48,26.16 ; TP19.1 124.61,25.25 ; TP19.1 124.61,27.08 ; TP19.1 123.7,24.94 ; J7.3 72.97,67.32 ; J7.3 72.97,63.99 ; J7.3 74.2,66.89 ; J7.3 71.75,64.43 ; J7.3 74.2,64.43 ; J7.3 71.75,66.89 ; J7.3 71.31,65.66 ; J7.3 74.64,65.66 ; 127.61,58.61 J13.5 ; J13.5 126.38,61.5 ; J13.5 127.61,61.94 ; J13.5 129.27,60.27 ; J13.5 126.38,59.05 ; J13.5 128.84,59.05 ; J13.5 125.95,60.27 ; J13.5 128.84,61.5 ; J7.2 69.12,64.43 ; J7.2 67.89,63.99 ; J7.2 69.12,66.89 ; J7.2 66.67,64.43 ; J7.2 66.23,65.66 ; J7.2 66.67,66.89 ; J7.2 69.56,65.66 ; J7.2 67.89,67.32 ; TP6.1 105.94,23.52 ; TP6.1 104.12,21.69 ; TP6.1 105.03,21.39 ; TP6.1 103.81,22.61 ; TP6.1 106.25,22.61 ; TP6.1 105.94,21.69 ; TP6.1 104.12,23.52 ; TP6.1 105.03,23.83 ; MT2.1 17.78,19.99 ; MT2.1 19.39,19.39 ; MT2.1 19.39,16.17 ; MT2.1 19.99,17.78 ; MT2.1 16.17,19.39 ; MT2.1 15.57,17.78 ; MT2.1 16.17,16.17 ; MT2.1 17.78,15.57 ; 22.35,54.48 23.52,54.48 ; 22.35,54.48 22.35,53.31 ; 22.35,54.48 21.18,54.48 ; 22.35,54.48 23.23,55.36 ; 22.35,54.48 23.23,53.61 ; 22.35,54.48 22.35,55.65 ; 22.35,54.48 21.47,55.36 ; 22.35,54.48 21.47,53.61 ; 115.42,4.34 TP11.1 ; TP11.1 117.55,3.43 ; TP11.1 115.11,3.43 ; TP11.1 116.33,2.21 ; TP11.1 117.25,4.34 ; TP11.1 117.25,2.52 ; TP11.1 116.33,4.65 ; TP11.1 115.42,2.52 ; JP1.3 99.94,27.67 ; JP1.3 99.06,25.63 ; JP1.3 98.18,25.92 ; JP1.3 98.18,27.67 ; JP1.3 97.89,26.8 ; JP1.3 99.94,25.92 ; JP1.3 99.06,27.97 ; JP1.3 100.23,26.8 ; 131.46,66.58 J13.3 ; J13.3 131.46,64.13 ; J13.3 133.92,66.58 ; J13.3 132.69,63.69 ; J13.3 134.35,65.35 ; J13.3 132.69,67.02 ; J13.3 133.92,64.13 ; J13.3 131.03,65.35 ; JP5.2 22.35,32.16 ; JP5.2 21.18,30.99 ; JP5.2 21.47,30.11 ; JP5.2 22.35,29.82 ; JP5.2 23.23,31.87 ; JP5.2 23.23,30.11 ; JP5.2 23.52,30.99 ; JP5.2 21.47,31.87 ; J7.5 69.12,59.35 ; J7.5 66.67,59.35 ; J7.5 69.12,61.81 ; J7.5 69.56,60.58 ; J7.5 67.89,62.24 ; J7.5 66.23,60.58 ; J7.5 66.67,61.81 ; J9.5 128.84,48.25 ; J9.5 129.27,49.48 ; J9.5 125.95,49.48 ; J9.5 126.38,50.71 ; J9.5 127.61,47.81 ; J9.5 126.38,48.25 ; J7.4 74.2,61.81 ; J7.4 71.75,61.81 ; J7.4 74.2,59.35 ; J7.4 71.31,60.58 ; J7.4 71.75,59.35 ; J7.4 74.64,60.58 ; 55.68,16.64 TP14.1 ; TP14.1 56.9,15.42 ; TP14.1 55.98,17.55 ; TP14.1 57.81,17.55 ; TP14.1 58.12,16.64 ; TP14.1 55.98,15.72 ; TP14.1 56.9,17.86 ; TP14.1 57.81,15.72 ; J13.4 134.35,60.27 ; J13.4 132.69,58.61 ; J13.4 133.92,61.5 ; J13.4 132.69,61.94 ; J13.4 131.46,59.05 ; J13.4 131.46,61.5 ; J13.4 133.92,59.05 ; J13.4 131.03,60.27 ; JP3.2 43.28,63.35 ; JP3.2 40.94,63.35 ; JP3.2 41.24,62.47 ; JP3.2 42.99,62.47 ; JP3.2 42.11,62.18 ; JP3.2 42.99,64.22 ; JP3.2 41.24,64.22 ; JP3.2 42.11,64.52 ; 127.61,63.69 J13.2 ; J13.2 128.84,64.13 ; J13.2 126.38,64.13 ; J13.2 129.27,65.35 ; J13.2 126.38,66.58 ; J13.2 128.84,66.58 ; J13.2 127.61,67.02 ; J13.2 125.95,65.35 ; 46.84,65.05 JP2.1 ; JP2.1 48.01,65.05 ; JP2.1 46.84,66.22 ; JP2.1 49.17,65.05 ; JP2.1 49.17,67.39 ; JP2.1 48.01,67.39 ; JP2.1 46.84,67.39 ; JP2.1 49.17,66.22 ; J9.3 134.35,54.56 ; J9.3 133.92,53.33 ; J9.3 133.92,55.79 ; J9.3 131.46,53.33 ; J9.3 131.03,54.56 ; J9.3 132.69,56.22 ; J9.3 131.46,55.79 ; 37.82,3.89 TP18.1 ; TP18.1 41.02,3.89 ; TP18.1 39.42,5.49 ; TP18.1 38.24,2.7 ; TP18.1 39.42,2.29 ; TP18.1 40.6,2.7 ; TP18.1 40.6,5.07 ; 31.93,0.89 J8.3 ; J8.3 30.22,1.52 ; J8.3 29.59,3.23 ; J8.3 33.63,1.52 ; J8.3 34.27,3.23 ; J8.3 30.22,4.93 ; 26.97,6.32 J8.2 ; J8.2 31.01,8.03 ; J8.2 28.68,10.36 ; J8.2 26.34,8.03 ; J8.2 26.97,9.73 ; J8.2 28.68,5.69 ; J8.2 30.38,9.73 ; J8.2 30.38,6.32 ; 131.46,48.25 J9.4 ; J9.4 133.92,50.71 ; J9.4 134.35,49.48 ; J9.4 131.03,49.48 ; J9.4 132.69,47.81 ; J9.2 127.61,56.22 ; J9.2 126.38,53.33 ; J9.2 128.84,55.79 ; J9.2 125.95,54.56 ; J9.2 129.27,54.56 ; J9.2 128.84,53.33
  BOTTOM w0.483: 46.23,45.41 v3(46.19,45.37) ; R32.2 43.56,38.79 v3(43.56,38.79)
  BOTTOM w0.508: J10.B22 148.59,32.54 v3(147.98,33.15) ; C32.2 v1(24.77,39.24) ; J10.K15 138.4,41.4 v3(138.18,41.63) ; v3(131.93,8.2) v3(132.94,9.22) ; v3(139.09,39.5) 139.7,38.89 J10.J17 ; v3(141.58,40.72) 141.61,40.74 141.63,40.74 J10.H15 ; C34.2 v1(24.77,38.1) ; J10.G4 142.27,55.37 v3(142.75,54.89) ; v3(146.71,33.12) 146.1,32.51 J10.D22 ; v3(138.43,56.64) 138.43,56.62 v3(138.99,56.06) ; C25.2 v1(24.77,47.37) ; J10.A21 v1(150.55,33.1) ; C29.2 v1(24.77,46.23) ; J10.A20 v3(149.3,35.61)
  vias: v1(0.51,67.94) v1(0.51,0.64) v1(0.54,65.91) v1(0.57,62.46) v1(0.61,61.21) v1(0.54,58.29) v1(0.57,52.3) v1(0.61,51.08) v1(0.54,48.13) v1(0.57,46.04) v1(0.54,43.05) v1(0.54,41.87) v1(0.57,37.36) v1(0.54,35.43) v1(0.54,33.2) v1(0.57,27.2) v1(0.54,25.27) v1(0.54,23.04) v1(0.54,17.65) v1(0.54,15.11) v1(0.54,12.57) v1(0.54,10.03) v1(0.54,7.49) v1(0.54,4.95) v1(0.54,2.41) v1(0.64,59.49) v1(0.64,49.35) v1(0.81,25.93) v1(0.79,24.26) v1(1.04,36.17) v1(1.04,34.39) v1(1.65,51.08) v1(1.65,49.35) v1(1.84,62.46) v1(1.84,58.27) v1(1.84,52.3) v1(1.84,48.11) v1(1.84,46.04) v1(1.84,41.85) v1(1.84,37.36) v1(1.84,33.17) v1(1.84,27.2) v1(1.84,23.01) v1(1.91,0.64) v1(1.96,61.24) v1(1.98,59.51) v1(2.29,25.93) v1(2.26,24.26) v1(2.41,67.94) v1(2.79,51.08) v1(2.79,49.35) v1(2.84,36.17) v1(2.84,34.39) v1(3.11,62.46) v1(3.11,58.27) v1(3.11,52.3) v1(3.11,48.11) v1(3.11,46.04) v1(3.11,41.85) v1(3.11,37.36) v1(3.11,33.17) v1(3.11,27.2) v1(3.11,23.01) v1(3.18,61.24) v1(3.2,59.51) v1(3.81,0.64) v1(3.84,51.08) v1(3.86,49.33) v1(3.89,25.96) v1(3.86,24.28) v1(4.32,67.94) v1(4.29,36.14) v1(4.29,34.37) v1(4.24,9.09) v1(4.38,62.46) v1(4.38,58.27) v1(4.38,52.3) v1(4.38,48.11) v1(4.38,46.04) v1(4.38,41.85) v1(4.38,37.36) v1(4.38,33.17) v1(4.38,27.2) v1(4.38,23.01) v1(4.83,61.47) v1(4.83,59.44) v1(5.21,51.31) v1(5.21,49.28) v1(5.33,36.32) v1(5.33,34.29) v1(5.33,26.16) v1(5.33,24.13) v1(5.65,62.46) v1(5.65,58.27) v1(5.65,52.3) v1(5.65,48.11) v1(5.65,46.04) v1(5.65,41.85) v1(5.65,37.36) v1(5.65,33.17) v1(5.65,27.2) v1(5.65,23.01) v1(5.72,0.64) v1(6.22,67.94) v1(6.35,1.4) v1(6.48,61.47) v1(6.48,54.36) v1(6.86,52.96) v1(6.86,51.31) v1(6.86,49.28) v1(6.99,36.32) v1(6.99,34.29) v1(6.99,32.89) v1(7.42,3.28) v1(7.62,54.86) v1(7.62,0.64) v1(7.87,30.61) v1(8.13,67.94) v1(8.26,49.53) v1(8.38,61.59) v1(8.38,35.81) v1(8.64,10.13) v1(9.02,55.37) v1(9.02,52.96) v1(9.02,50.8) v1(9.02,34.67) v1(9.14,32.39) v1(9.14,30.1) v1(9.53,51.82) v1(9.53,33.27) v1(9.53,0.64) v1(9.59,41.4) v1(9.78,50.67) v1(9.78,49.4) v1(9.78,48.13) v1(9.78,46.86) v1(9.78,38.73) v1(9.78,37.47) v1(9.78,36.2) v1(9.78,34.92) v1(9.91,52.96) v1(9.91,44.96) v1(9.91,40.39) v1(9.91,32.39) v1(10.03,67.94) v1(10.03,42.67) v1(10.22,41.4) v1(10.54,55.25) v1(10.8,30.35) v1(10.86,41.4) v1(11.25,5.56) v1(11.43,0.64) v1(11.68,54.36) v1(11.94,67.94) v1(11.94,38.73) v1(11.94,37.47) v1(11.94,36.2) v1(11.94,34.92) v1(12.07,49.4) v1(12.07,48.13) v1(12.07,46.86) v1(12.07,43.43) v1(12.07,42.04) v1(12.45,45.47) v1(12.45,40.01) v1(13.34,0.64) v1(13.84,67.94) v1(14.1,50.67) v1(14.1,49.4) v1(14.1,48.13) v1(14.1,46.86) v1(14.1,38.73) v1(14.1,37.47) v1(14.1,36.2) v1(14.1,34.92) v1(14.86,46.74) v1(14.86,43.31) v1(14.86,42.16) v1(14.86,38.73) v1(15.24,0.64) v1(15.75,67.94) v1(15.88,47.75) v1(15.88,37.85) v1(17.02,47.5) v1(17.02,37.97) v1(17.14,0.64) v1(17.91,67.94) v1(18.67,46.1) v1(18.67,39.37) v1(19.05,0.64) v1(19.69,67.94) v1(19.94,44.96) v1(19.94,40.51) v1(20.96,0.64) v1(21.34,47.62) v1(21.34,37.85) v1(21.46,67.94) v1(22.86,0.64) v1(23.37,67.94) v1(24.77,2.54) v1(24.77,0.64) v1(25.27,67.94) v1(26.44,4.95) v1(26.67,0.64) v1(27.18,67.94) v1(28.17,2.51) v1(28.58,0.64) v1(28.83,45.34) v1(29.08,67.94) v1(30.35,40.56) v1(30.48,47.57) v1(30.48,0.64) v1(30.68,44.78) v1(30.66,17.83) v1(30.77,5.8) v1(30.91,19.46) v1(30.99,67.94) v1(30.94,42.77) v1(30.99,16.54) v1(31.14,14.27) v1(31.14,11.23) v1(31.6,38.86) v1(31.57,36.73) v1(31.7,35.84) v1(31.75,46.36) v1(31.9,45.54) v1(32.21,39.67) v1(32.39,0.64) v1(32.72,16.54) v1(32.89,67.94) v1(33.38,48.16) v1(33.78,44.48) v1(33.83,40.82) v1(33.88,35.56) v1(34.29,0.64) v1(34.62,46.81) v1(34.67,67.94) v1(34.67,38.89) v1(34.67,36.6) v1(34.72,35.56) v1(35.1,44.55) v1(35.1,43.79) v1(35.08,41.61) v1(35.08,40.84) v1(35.13,4.04) v1(35.43,38.53) v1(35.56,50.34) v1(35.59,35.71) v1(35.74,36.83) v1(35.76,13.59) v1(35.76,11.86) v1(36.2,0.64) v1(36.25,40.31) v1(36.58,67.94) v1(36.7,48.95) v1(36.73,35.53) v1(36.68,23.06) v1(36.8,37.34) v1(36.83,2.18) v1(37.82,35.66) v1(37.8,13.61) v1(37.92,50.11) v1(37.9,11.86) v1(38.02,49.78) v1(38.13,16.21) v1(38.1,0.64) v1(38.15,21.44) v1(38.15,20.75) v1(38.15,18.19) v1(38.61,67.94) v1(38.53,57.45) v1(38.58,35.66) v1(38.63,55.65) v1(38.79,49.78) v1(38.82,21.42) v1(38.82,20.77) v1(38.82,18.17) v1(38.82,16.22) v1(38.96,35.05) v1(39.13,50.32) v1(39.24,62.94) v1(39.29,54.97) v1(39.47,21.44) v1(39.47,20.75) v1(39.5,18.16) v1(39.5,16.21) v1(39.55,59.56) v1(39.75,54.48) v1(39.94,13.62) v1(40.01,0.64) v1(40.28,11.86) v1(40.41,57.45) v1(40.51,67.94) v1(40.44,18.47) v1(40.44,16.43) v1(40.74,55.47) v1(40.97,53.16) v1(41.02,5.49) v1(41.28,32.99) v1(41.25,12.27) v1(41.35,31.09) v1(41.35,29.29) v1(41.63,35) v1(41.81,56.62) v1(41.79,13.6) v1(41.87,50.91) v1(41.91,0.64) v1(41.96,54.13) v1(41.99,27.51) v1(41.94,21.46) v1(41.94,20.4) v1(42.24,23.11) v1(42.42,67.94) v1(42.55,25.4) v1(42.75,57.56) v1(42.9,20.92) v1(43.03,55.19) v1(43.03,33.05) v1(43,31.09) v1(42.95,29.29) v1(43.08,35) v1(43.23,12.22) v1(43.4,50.93) v1(43.43,19.25) v1(43.66,58.47) v1(43.81,60.96) v1(43.81,0.64) v1(43.87,21.49) v1(43.84,20.37) v1(43.97,56.18) v1(44.32,67.94) v1(44.48,59.28) v1(44.73,55.63) v1(44.7,53.21) v1(44.93,57.12) v1(45.21,60.02) v1(45.21,35.56) v1(45.42,33.07) v1(45.39,18.82) v1(45.44,49.78) v1(45.47,35) v1(45.47,31.09) v1(45.47,29.26) v1(45.69,57.89) v1(45.72,0.64) v1(45.97,56.31) v1(46.06,18.84) v1(46.05,13.44) v1(46.23,67.94) v1(46.23,60.81) v1(46.2,49.27) v1(46.36,63.5) v1(46.36,25.4) v1(46.48,54.23) v1(46.51,35.03) v1(46.46,33.1) v1(46.51,31.12) v1(46.51,29.29) v1(46.56,53.39) v1(46.63,58.55) v1(46.71,18.82) v1(46.99,56.13) v1(46.97,50.06) v1(47.07,57.38) v1(47.22,47.7) v1(47.17,2.74) v1(47.25,50.94) v1(47.42,60.83) v1(47.4,59.03) v1(47.4,35.03) v1(47.47,27.28) v1(47.62,0.64) v1(47.9,33.1) v1(47.96,31.12) v1(47.96,29.29) v1(48.06,4.78) v1(48.13,67.94) v1(48.31,61.52) v1(48.29,58.27) v1(48.67,7.01) v1(48.89,53.09) v1(48.89,11.43) v1(48.97,61.01) v1(49,58.83) v1(48.94,51.03) v1(48.95,49.35) v1(48.97,46.76) v1(48.97,42.67) v1(49.05,44.5) v1(49.2,3.38) v1(49.38,33.05) v1(49.43,31.06) v1(49.43,29.24) v1(49.38,21.23) v1(49.58,58.45) v1(49.53,0.64) v1(49.73,46.99) v1(49.73,44.83) v1(49.73,42.67) v1(49.73,40.51) v1(49.73,38.35) v1(49.76,36.2) v1(49.99,27.33) v1(50.04,67.94) v1(50.14,60.81) v1(50.19,57.91) v1(50.16,57.15) v1(50.22,56.34) v1(50.16,13.97) v1(50.32,62.1) v1(50.39,55.37) v1(50.6,67.08) v1(50.6,65.96) v1(50.67,54) v1(50.72,25.98) v1(50.67,8.61) v1(50.67,7.52) v1(50.9,33.05) v1(50.95,31.06) v1(50.95,29.24) v1(51.03,6.35) v1(51.28,51.18) v1(51.28,49.23) v1(51.28,46.99) v1(51.28,44.81) v1(51.31,42.62) v1(51.31,40.54) v1(51.31,38.35) v1(51.31,36.2) v1(51.41,67.08) v1(51.41,65.96) v1(51.46,60.78) v1(51.51,59.05) v1(51.44,17.78) v1(51.44,0.64) v1(51.66,53.01) v1(51.64,8.06) v1(51.94,67.94) v1(52.02,62.66) v1(52.02,58.27) v1(51.99,57.07) v1(52.07,63.27) v1(52.12,62.15) v1(52.22,55.12) v1(52.32,64.21) v1(52.35,59.92) v1(52.37,35.69) v1(52.43,33.05) v1(52.48,31.06) v1(52.48,29.24) v1(52.55,52.15) v1(52.58,8.61) v1(52.58,7.54) v1(52.7,11.43) v1(52.78,40.54) v1(52.81,38.38) v1(52.73,25.43) v1(52.96,57.68) v1(52.93,54.89) v1(52.93,23.52) v1(53.09,47.02) v1(53.26,53.98) v1(53.26,42.67) v1(53.34,0.64) v1(53.47,57.18) v1(53.47,51.18) v1(53.52,49.17) v1(53.59,44.83) v1(53.62,35.05) v1(53.75,64.9) v1(53.75,54.58) v1(53.85,67.94) v1(53.95,58.06) v1(53.98,20.32) v1(53.98,16.51) v1(54.05,53.24) v1(54.13,7.21) v1(54.18,40.54) v1(54.15,22.35) v1(54.15,8.03) v1(54.48,53.85) v1(54.58,58.45) v1(54.61,36.93) v1(54.71,7.62) v1(54.71,2.39) v1(54.89,52.4) v1(54.91,33.12) v1(54.99,64.54) v1(54.99,47.02) v1(54.97,31.06) v1(54.94,29.29) v1(55.22,42.67) v1(55.25,13.97) v1(55.3,8.03) v1(55.27,7.24) v1(55.25,0.64) v1(55.55,53.11) v1(55.6,49.1) v1(55.75,67.94) v1(55.85,38.96) v1(56.08,52.4) v1(56.08,51.18) v1(56.11,44.86) v1(56.41,35.15) v1(56.49,55.47) v1(56.45,25.96) v1(56.44,21.08) v1(56.52,11.43) v1(56.59,65.81) v1(56.9,41.07) v1(57.12,54.56) v1(57.18,66.5) v1(57.23,47.02) v1(57.15,0.64) v1(57.28,55.47) v1(57.45,51.18) v1(57.53,37.21) v1(57.56,2.39) v1(57.66,67.94) v1(57.68,52.91) v1(57.81,31.09) v1(57.79,29.29) v1(57.79,19.05) v1(57.84,67.16) v1(57.89,43.1) v1(57.96,33.1) v1(58.29,49.12) v1(58.42,46.28) v1(58.6,56.77) v1(58.7,55.7) v1(58.67,39.32) v1(58.78,67.16) v1(58.75,51.18) v1(58.88,35.15) v1(59,45.26) v1(59.05,22.86) v1(59.05,0.64) v1(59.36,57.05) v1(59.36,54.56) v1(59.46,52.88) v1(59.56,67.94) v1(59.59,41.45) v1(59.69,67.16) v1(59.66,9.58) v1(59.82,47.6) v1(60.07,59.39) v1(60.07,44.27) v1(60.2,50.04) v1(60.2,20.68) v1(60.17,8.84) v1(60.2,2.51) v1(60.3,65.51) v1(60.25,56.64) v1(60.33,27.18) v1(60.33,25.4) v1(60.33,16.71) v1(60.4,54.58) v1(60.4,52.88) v1(60.4,47.24) v1(60.71,19.94) v1(60.73,67.03) v1(60.73,65.61) v1(60.83,43.46) v1(60.88,37.19) v1(61.01,58.37) v1(60.96,0.64) v1(61.06,21.84) v1(61.14,64.44) v1(61.19,31.09) v1(61.24,33.1) v1(61.24,29.31) v1(61.42,6.88) v1(61.39,6.07) v1(61.47,67.94) v1(61.52,67.08) v1(61.57,65.61) v1(61.54,58.01) v1(61.57,54.61) v1(61.62,52.88) v1(61.54,48.69) v1(61.62,39.29) v1(61.59,24.26) v1(61.59,23.11) v1(61.65,35.13) v1(61.9,41.35) v1(61.98,56.72) v1(62,45.52) v1(61.98,6.48) v1(62.13,26.34) v1(62.13,25.5) v1(62.2,58.83) v1(62.36,64.49) v1(62.36,61.95) v1(62.43,60.83) v1(62.48,54.74) v1(62.56,6.88) v1(62.53,6.1) v1(62.92,25.91) v1(62.87,0.64) v1(63.02,67.03) v1(62.99,65.58) v1(62.97,53.11) v1(62.94,47.27) v1(63.2,57.79) v1(63.37,67.94) v1(63.37,60.83) v1(63.35,37.16) v1(63.5,64.47) v1(63.63,60.22) v1(63.7,26.34) v1(63.7,25.5) v1(63.78,67.03) v1(63.86,65.58) v1(64.01,61.72) v1(64.01,53.72) v1(64.19,47.27) v1(64.21,45.44) v1(64.21,41.33) v1(64.13,2.54) v1(64.24,60.83) v1(64.26,49.53) v1(64.24,43.43) v1(64.24,39.24) v1(64.31,35.1) v1(64.39,56.49) v1(64.34,32.99) v1(64.39,31.06) v1(64.44,29.26) v1(64.52,26.62) v1(64.54,67.03) v1(64.62,65.61) v1(64.62,64.49) v1(64.59,62.99) v1(64.59,61.93) v1(64.8,54.51) v1(64.74,37.16) v1(64.77,0.64) v1(64.87,57.15) v1(65.07,59.44) v1(65.28,67.94) v1(65.33,67.08) v1(65.58,55.3) v1(65.91,60.48) v1(66.01,65.61) v1(66.01,64.49) v1(66.04,62.99) v1(66.07,61.85) v1(66.19,59.21) v1(66.62,47.29) v1(66.55,12.83) v1(66.65,45.47) v1(66.68,43.46) v1(66.65,41.35) v1(66.68,39.27) v1(66.73,37.24) v1(66.68,0.64) v1(66.75,35.13) v1(66.78,33.02) v1(66.83,31.09) v1(66.88,29.29) v1(66.95,11.56) v1(67.03,56.77) v1(67.18,67.94) v1(67.51,49.25) v1(67.67,10.41) v1(67.69,9.27) v1(67.94,55.12) v1(67.94,51.56) v1(67.94,2.54) v1(68.05,57.35) v1(68.07,9.83) v1(68.48,10.39) v1(68.48,9.25) v1(68.58,0.64) v1(68.91,47.35) v1(68.94,45.52) v1(68.96,43.51) v1(68.94,41.4) v1(68.96,39.32) v1(69.01,37.29) v1(68.96,5.69) v1(69.09,67.94) v1(69.04,35.18) v1(69.06,33.07) v1(69.11,31.14) v1(69.22,57.48) v1(69.16,29.34) v1(69.19,26.77) v1(69.22,24.13) v1(69.19,20.85) v1(69.22,12.7) v1(69.37,59.18) v1(69.34,49.53) v1(69.77,52.91) v1(69.77,52.1) v1(69.93,8.1) v1(70.21,57.45) v1(70.36,59.16) v1(70.36,52.5) v1(70.48,0.64) v1(70.92,52.91) v1(70.89,52.15) v1(70.99,67.94) v1(71.22,47.32) v1(71.25,45.49) v1(71.27,43.48) v1(71.25,41.38) v1(71.27,39.29) v1(71.32,37.26) v1(71.25,8.89) v1(71.25,5.08) v1(71.35,57.45) v1(71.35,35.15) v1(71.37,33.05) v1(71.42,31.12) v1(71.37,29.29) v1(71.5,59.16) v1(71.91,61.98) v1(72.15,18.94) v1(72.15,17.77) v1(72.15,16.63) v1(72.15,15.49) v1(72.24,63.83) v1(72.39,0.64) v1(72.52,12.7) v1(72.52,2.54) v1(72.62,52.93) v1(72.64,52.15) v1(72.82,57.48) v1(72.9,67.94) v1(73.03,17.78) v1(73.2,52.53) v1(73.58,47.27) v1(73.61,45.44) v1(73.61,41.33) v1(73.63,43.43) v1(73.63,39.24) v1(73.69,37.21) v1(73.71,35.1) v1(73.76,52.93) v1(73.79,52.12) v1(73.74,32.99) v1(73.79,31.06) v1(73.84,29.26) v1(74.01,63.8) v1(74.12,61.95) v1(74.04,57.48) v1(74.24,59.16) v1(74.3,24.13) v1(74.3,0.64) v1(74.42,49.53) v1(74.4,20.83) v1(74.8,67.94) v1(74.78,16.71) v1(74.9,9.96) v1(75.01,63.7) v1(75.03,61.9) v1(75.13,59.18) v1(75.16,57.38) v1(75.18,26.72) v1(75.23,60.58) v1(75.32,2.97) v1(75.39,9.17) v1(75.49,52.91) v1(75.51,52.15) v1(75.56,66.04) v1(75.72,47.27) v1(75.74,45.44) v1(75.77,43.43) v1(75.74,41.33) v1(75.77,39.24) v1(75.82,37.21) v1(75.84,35.1) v1(75.87,32.99) v1(75.92,31.06) v1(75.97,29.26) v1(76.07,63.68) v1(76.07,52.53) v1(76.2,0.64) v1(76.71,67.94) v1(76.63,52.91) v1(76.63,52.15) v1(76.71,6.91) v1(76.68,6.1) v1(76.78,57.38) v1(76.84,21.59) v1(76.96,60.6) v1(76.96,59.21) v1(77.16,63.8) v1(77.19,61.95) v1(77.27,6.5) v1(77.44,47.27) v1(77.47,45.44) v1(77.5,43.43) v1(77.47,41.33) v1(77.5,39.24) v1(77.55,37.21) v1(77.57,35.1) v1(77.6,32.99) v1(77.6,2.54) v1(77.65,31.06) v1(77.7,29.26) v1(77.83,6.12) v1(77.85,6.91) v1(77.98,59.21) v1(77.98,57.38) v1(78.11,0.64) v1(78.44,52.15) v1(78.61,67.94) v1(78.83,65.35) v1(78.79,63.68) v1(78.77,61.95) v1(78.89,35.13) v1(78.87,16.51) v1(78.87,5.08) v1(78.94,52.53) v1(79.22,59.21) v1(79.22,57.38) v1(79.3,47.29) v1(79.32,45.47) v1(79.32,41.35) v1(79.35,43.46) v1(79.35,39.27) v1(79.4,37.24) v1(79.38,24.13) v1(79.44,65.35) v1(79.5,52.17) v1(79.5,49.53) v1(79.45,33.02) v1(79.5,31.09) v1(79.55,29.29) v1(80.02,65.35) v1(80.01,0.64) v1(80.09,60.17) v1(80.21,61.98) v1(80.24,63.65) v1(80.29,57.81) v1(80.31,7.62) v1(80.34,26.75) v1(80.52,67.94) v1(80.8,31.12) v1(80.9,53.98) v1(80.85,47.24) v1(80.87,45.42) v1(80.9,43.41) v1(80.87,41.3) v1(80.9,39.22) v1(80.85,15.52) v1(81,61.09) v1(80.95,37.19) v1(81.03,29.29) v1(81.1,21.56) v1(81.25,58.8) v1(81.46,35.13) v1(81.58,63.65) v1(81.58,16.03) v1(81.58,8.03) v1(81.69,61.98) v1(81.66,57.38) v1(81.84,55.65) v1(81.92,0.64) v1(82.02,64.08) v1(82.25,59.74) v1(82.42,67.94) v1(82.4,33.07) v1(82.37,30.18) v1(82.58,66.19) v1(82.61,64.08) v1(82.8,47.27) v1(82.83,45.44) v1(82.83,41.33) v1(82.85,43.43) v1(82.85,39.24) v1(83.03,60.58) v1(83.21,64.08) v1(83.29,31.06) v1(83.52,37.16) v1(83.79,61.34) v1(83.82,0.64) v1(83.85,66.22) v1(83.87,64.52) v1(83.87,63.83) v1(84.02,59.84) v1(84.05,57.89) v1(84.33,67.94) v1(84.4,35.1) v1(84.51,55.6) v1(84.58,62.08) v1(84.58,49.53) v1(85.09,62.66) v1(85.06,47.24) v1(85.09,45.42) v1(85.12,43.41) v1(85.09,41.3) v1(85.09,31.09) v1(85.22,33.02) v1(85.22,28.04) v1(85.22,16.69) v1(85.42,65.53) v1(85.55,61.57) v1(85.65,39.29) v1(85.72,0.64) v1(85.93,62.97) v1(85.95,59.84) v1(86.21,66.27) v1(86.23,67.94) v1(86.48,24.29) v1(86.49,8.89) v1(86.54,37.19) v1(86.66,63.02) v1(87.02,67.11) v1(87.12,47.29) v1(87.15,45.47) v1(87.17,43.46) v1(87.33,35.1) v1(87.33,33.05) v1(87.25,31.09) v1(87.43,63.17) v1(87.55,60.17) v1(87.63,26.21) v1(87.63,0.64) v1(87.71,41.33) v1(87.7,24.67) v1(88.06,67.18) v1(88.09,61.87) v1(88.14,67.94) v1(88.21,65.38) v1(88.29,63.22) v1(88.39,49.53) v1(88.57,47.9) v1(88.57,20.57) v1(88.67,59.36) v1(88.67,39.27) v1(88.87,24.69) v1(89.1,67.13) v1(89.2,65.38) v1(89.23,45.49) v1(89.28,37.08) v1(89.28,25) v1(89.38,64.67) v1(89.36,62.89) v1(89.33,35.13) v1(89.36,33.05) v1(89.38,31.09) v1(89.53,49.02) v1(89.53,0.64) v1(89.66,25.28) v1(89.79,47.42) v1(89.84,43.43) v1(89.89,5.72) v1(90.04,67.94) v1(90.12,67.28) v1(90.12,62.89) v1(90.22,65.46) v1(90.14,64.64) v1(90.58,20.4) v1(90.6,19.58) v1(90.73,41.33) v1(90.81,27.94) v1(90.98,16.28) v1(90.98,10.54) v1(91.36,19.96) v1(91.44,39.27) v1(91.44,37.16) v1(91.52,35.13) v1(91.49,33.05) v1(91.44,0.64) v1(91.57,31.09) v1(91.74,45.47) v1(91.83,49.11) v1(91.95,67.94) v1(92.13,20.37) v1(92.13,19.56) v1(92.48,43.41) v1(93.34,0.64) v1(93.55,64.44) v1(93.85,67.94) v1(93.85,50.42) v1(93.93,43.41) v1(93.9,41.3) v1(93.85,39.29) v1(93.88,37.13) v1(93.9,35.13) v1(93.9,33.05) v1(93.93,31.04) v1(93.95,45.49) v1(94.07,49.11) v1(94.11,22.86) v1(94.11,8.89) v1(94.87,67.41) v1(94.88,49.11) v1(94.89,47.45) v1(95.12,50.42) v1(95.25,0.64) v1(95.45,64.39) v1(95.76,67.94) v1(95.81,41.28) v1(95.76,39.27) v1(95.78,37.11) v1(95.81,35.1) v1(95.81,33.02) v1(95.78,6.81) v1(95.86,51.38) v1(95.86,45.47) v1(95.83,43.38) v1(95.83,31.01) v1(95.89,19.05) v1(95.89,13.97) v1(95.89,2.54) v1(95.94,16.87) v1(97.1,67.41) v1(97.11,49.11) v1(97.17,49.9) v1(97.16,0.64) v1(97.26,47.29) v1(97.41,50.72) v1(97.66,67.94) v1(97.82,39.32) v1(97.89,43.43) v1(97.87,41.33) v1(97.84,37.16) v1(97.87,35.15) v1(97.87,33.07) v1(97.89,31.06) v1(98.37,45.44) v1(98.68,11.4) v1(98.98,66.09) v1(98.96,11) v1(99.06,0.64) v1(99.19,51.33) v1(99.21,17.48) v1(99.21,4.27) v1(99.24,47.98) v1(99.24,10.59) v1(99.4,49.9) v1(99.39,49.12) v1(99.52,65.2) v1(99.57,67.94) v1(99.7,2.54) v1(99.9,47.24) v1(99.92,45.42) v1(99.92,41.3) v1(99.95,43.41) v1(99.95,39.22) v1(100,37.19) v1(100.03,35.08) v1(100.05,32.97) v1(100.1,31.04) v1(100.15,29.24) v1(100.43,65.4) v1(100.48,17.07) v1(100.43,8.38) v1(100.43,7.54) v1(100.61,59.26) v1(100.63,57.43) v1(100.71,53.47) v1(100.76,55.45) v1(100.86,47.75) v1(100.99,7.95) v1(100.97,0.64) v1(101.47,67.94) v1(101.63,53.75) v1(101.63,17.37) v1(101.6,16.54) v1(101.55,8.38) v1(101.55,7.54) v1(101.65,55.5) v1(101.85,65.51) v1(102.01,47.24) v1(102.06,59.44) v1(102.06,57.2) v1(102.03,45.42) v1(102.06,43.41) v1(102.03,41.3) v1(102.06,39.22) v1(102.11,37.19) v1(102.13,35.08) v1(102.16,32.97) v1(102.21,31.04) v1(102.23,49.53) v1(102.39,16.97) v1(102.75,65.42) v1(102.87,0.64) v1(103.1,55.55) v1(103.18,53.23) v1(103.15,17.37) v1(103.15,16.56) v1(103.38,67.94) v1(103.5,25.4) v1(103.5,2.54) v1(103.56,59.41) v1(103.56,57.2) v1(103.91,47.24) v1(103.94,45.42) v1(103.96,43.41) v1(103.94,41.3) v1(103.96,39.22) v1(104.01,37.19) v1(104.06,52.02) v1(104.04,35.08) v1(104.06,32.97) v1(104.11,31.04) v1(104.22,62.33) v1(104.72,59.21) v1(104.7,57.4) v1(104.77,54.81) v1(104.78,5.08) v1(104.78,0.64) v1(105,65.53) v1(105.11,63.07) v1(105.28,67.94) v1(105.26,51.28) v1(105.64,56.46) v1(105.82,47.24) v1(105.89,65.53) v1(105.89,63.07) v1(105.84,45.42) v1(105.87,43.41) v1(105.84,41.3) v1(105.87,39.22) v1(105.92,37.19) v1(105.94,58.72) v1(105.99,53.87) v1(105.94,35.08) v1(105.97,32.97) v1(106.02,31.04) v1(106.02,9.47) v1(106.05,60.96) v1(106.05,27.94) v1(106.05,19.05) v1(106.05,12.7) v1(106.17,17.65) v1(106.17,16.64) v1(106.53,55.55) v1(106.5,53.21) v1(106.48,51.16) v1(106.65,65.56) v1(106.65,63.04) v1(106.68,0.64) v1(106.88,57.79) v1(107.06,17.65) v1(107.06,16.64) v1(107.19,67.94) v1(107.31,49.53) v1(107.37,65.43) v1(107.37,63.17) v1(107.44,54.64) v1(107.7,53.19) v1(107.67,51.13) v1(107.72,47.24) v1(107.77,56.87) v1(107.75,45.42) v1(107.77,43.41) v1(107.75,41.3) v1(107.77,39.22) v1(107.82,37.19) v1(107.77,21.72) v1(107.85,35.08) v1(107.87,32.97) v1(107.92,31.04) v1(108.15,65.2) v1(108.28,63.25) v1(108.28,62.05) v1(108.25,60.73) v1(108.28,59.26) v1(108.31,15.24) v1(108.31,13.97) v1(108.46,22.73) v1(108.59,2.54) v1(108.59,0.64) v1(108.69,55.96) v1(108.92,57.89) v1(108.92,51.13) v1(108.94,53.19) v1(109.09,67.94) v1(109.35,64.72) v1(109.47,55.22) v1(109.52,53.42) v1(109.63,47.24) v1(109.65,45.42) v1(109.68,43.41) v1(109.65,41.3) v1(109.68,39.22) v1(109.73,37.19) v1(109.75,35.08) v1(109.78,32.97) v1(109.83,31.04) v1(110.08,63.27) v1(110.08,62.08) v1(110.06,60.76) v1(110.08,59.28) v1(110.08,57.3) v1(110.36,53.21) v1(110.34,51.16) v1(110.49,0.64) v1(111,67.94) v1(110.97,60.2) v1(110.97,56.18) v1(111,55.22) v1(111.05,53.42) v1(111.12,27.94) v1(111.53,47.24) v1(111.56,45.42) v1(111.58,43.41) v1(111.56,41.3) v1(111.58,39.22) v1(111.63,37.19) v1(111.66,35.08) v1(111.68,32.97) v1(111.79,63.58) v1(111.73,31.04) v1(112.01,51.13) v1(111.96,21.16) v1(112.04,53.19) v1(112.39,49.53) v1(112.39,0.64) v1(112.9,67.94) v1(112.9,55.22) v1(112.95,53.42) v1(113.44,47.24) v1(113.46,45.42) v1(113.49,43.41) v1(113.46,41.3) v1(113.49,39.22) v1(113.54,37.19) v1(113.56,35.08) v1(113.59,32.97) v1(113.64,63.47) v1(113.64,31.04) v1(113.67,5.08) v1(113.67,2.54) v1(114,53.19) v1(113.97,51.13) v1(114.3,0.64) v1(114.4,8.23) v1(114.58,63.73) v1(114.81,67.94) v1(114.94,12.7) v1(115.09,55.19) v1(115.14,53.39) v1(115.34,47.24) v1(115.37,45.42) v1(115.39,43.41) v1(115.37,41.3) v1(115.39,39.22) v1(115.44,37.19) v1(115.47,35.08) v1(115.49,32.97) v1(115.54,31.04) v1(115.7,63.73) v1(116.03,51.13) v1(116.05,53.19) v1(116.2,66.04) v1(116.2,0.64) v1(116.71,67.94) v1(116.81,63.73) v1(116.84,55.25) v1(116.89,53.44) v1(117.17,25.78) v1(117.25,47.24) v1(117.27,45.42) v1(117.3,43.41) v1(117.27,41.3) v1(117.3,39.22) v1(117.35,37.19) v1(117.37,35.08) v1(117.4,32.97) v1(117.47,49.53) v1(117.45,31.04) v1(117.45,24.77) v1(117.47,13.97) v1(117.47,10.16) v1(117.63,51.13) v1(117.65,53.19) v1(117.86,23.5) v1(117.93,22.38) v1(117.93,21.56) v1(118.11,0.64) v1(118.36,55.22) v1(118.41,53.42) v1(118.49,22.38) v1(118.49,21.56) v1(118.52,7.57) v1(118.62,67.94) v1(118.75,27.94) v1(118.75,17.78) v1(118.75,2.54) v1(119.2,63.47) v1(119.22,56.21) v1(119.15,47.24) v1(119.18,45.42) v1(119.2,43.41) v1(119.18,41.3) v1(119.2,39.22) v1(119.28,57.66) v1(119.25,37.19) v1(119.28,35.08) v1(119.3,32.97) v1(119.38,53.19) v1(119.35,51.13) v1(119.35,31.04) v1(119.51,18.8) v1(119.81,16.13) v1(119.79,15.01) v1(120.02,66.04) v1(120.02,24.13) v1(120.02,0.64) v1(120.19,55.22) v1(120.24,53.42) v1(120.52,67.94) v1(120.68,16.13) v1(120.68,15.01) v1(120.98,19.28) v1(120.98,18.47) v1(121.06,47.24) v1(121.08,45.42) v1(121.11,43.41) v1(121.08,41.3) v1(121.11,39.22) v1(121.08,13.87) v1(121.08,12.75) v1(121.18,53.19) v1(121.16,51.13) v1(121.16,37.19) v1(121.18,35.08) v1(121.21,32.97) v1(121.26,31.04) v1(121.59,20.55) v1(121.54,19.28) v1(121.54,18.47) v1(121.92,0.64) v1(121.95,55.25) v1(122,53.44) v1(122.05,21.74) v1(122.25,22.68) v1(122.43,67.94) v1(122.43,56.21) v1(122.56,49.53) v1(122.96,47.24) v1(122.99,45.42) v1(123.01,43.41) v1(122.99,41.3) v1(123.01,39.22) v1(123.09,53.19) v1(123.06,51.13) v1(123.06,37.19) v1(123.09,35.08) v1(123.11,32.97) v1(123.16,31.04) v1(123.39,56.18) v1(123.83,2.54) v1(123.83,0.64) v1(123.88,55.22) v1(123.93,53.42) v1(124.33,67.94) v1(124.79,56.16) v1(124.87,53.64) v1(124.87,47.24) v1(124.89,45.42) v1(124.92,43.41) v1(124.89,41.3) v1(124.92,39.22) v1(124.97,37.19) v1(124.99,35.08) v1(125.02,32.97) v1(125.09,66.04) v1(125.07,31.04) v1(125.09,27.94) v1(125.53,51.13) v1(125.55,53.19) v1(125.65,56.97) v1(125.76,54.56) v1(125.73,0.64) v1(126.11,5.99) v1(126.24,67.94) v1(126.36,3.81) v1(126.49,57.81) v1(126.77,47.24) v1(126.8,45.42) v1(126.82,43.41) v1(126.8,41.3) v1(126.82,39.22) v1(126.9,51.13) v1(126.87,37.19) v1(126.9,35.08) v1(126.92,32.97) v1(126.97,31.04) v1(127.71,58.39) v1(127.64,0.64) v1(127.81,56.59) v1(128.14,67.94) v1(128.19,52.78) v1(128.32,16) v1(128.3,14.88) v1(128.27,7.62) v1(128.68,47.24) v1(128.7,45.42) v1(128.73,43.41) v1(128.7,41.3) v1(128.73,39.22) v1(128.78,37.19) v1(128.8,35.08) v1(128.83,32.97) v1(128.88,31.04) v1(128.91,25.4) v1(128.91,2.54) v1(129.18,16) v1(129.18,14.88) v1(129.41,61.16) v1(129.41,59.77) v1(129.39,53.59) v1(129.44,58.42) v1(129.44,56.59) v1(129.44,54.94) v1(129.62,18.9) v1(129.62,18.08) v1(129.62,13.74) v1(129.62,12.62) v1(129.54,0.64) v1(129.82,29.74) v1(130.05,67.94) v1(130.18,49.3) v1(130.18,18.9) v1(130.18,18.08) v1(130.25,20.17) v1(130.51,28.68) v1(130.58,47.24) v1(130.61,45.42) v1(130.61,41.3) v1(130.63,43.41) v1(130.63,39.22) v1(130.68,37.19) v1(130.71,35.08) v1(130.71,21.36) v1(130.73,32.97) v1(130.78,31.04) v1(130.76,22.35) v1(130.86,61.16) v1(130.89,59.77) v1(130.86,58.39) v1(130.86,56.59) v1(130.86,54.91) v1(130.86,53.57) v1(131.44,27.94) v1(131.44,0.64) v1(131.9,52.68) v1(131.95,67.94) v1(132.33,24.51) v1(132.49,47.24) v1(132.51,45.42) v1(132.51,41.3) v1(132.54,43.41) v1(132.54,39.22) v1(132.59,37.19) v1(132.61,35.08) v1(132.64,32.97) v1(132.69,31.04) v1(133.35,51.16) v1(133.35,0.64) v1(133.48,24.51) v1(133.86,67.94) v1(133.99,2.54) v1(134.06,46.05) v1(134.06,43.48) v1(134.24,53.24) v1(134.32,51.16) v1(134.52,41.38) v1(134.52,39.24) v1(134.52,37.19) v1(134.49,35.1) v1(134.44,33.02) v1(134.44,31.09) v1(134.59,49.48) v1(134.65,5.87) v1(135.25,62.23) v1(135.25,44.5) v1(135.25,0.64) v1(135.33,47.4) v1(135.76,67.94) v1(136.22,31.06) v1(136.27,53.26) v1(136.25,42.77) v1(136.27,39.8) v1(136.25,37.16) v1(136.3,33.02) v1(136.25,9.86) v1(136.42,51.18) v1(136.35,45.62) v1(136.37,35.13) v1(136.53,48.62) v1(136.53,5.08) v1(137.16,0.64) v1(137.39,43.89) v1(137.39,41) v1(137.34,38.02) v1(137.54,46.79) v1(137.54,31.06) v1(137.67,67.94) v1(137.74,35.69) v1(137.74,33.07) v1(138.21,7.85) v1(138.43,57.91) v1(138.43,45.21) v1(138.43,33.78) v1(138.43,29.97) v1(138.43,26.16) v1(138.43,22.35) v1(138.43,18.54) v1(138.43,14.73) v1(138.43,10.92) v1(139.06,2.54) v1(139.06,0.64) v1(139.34,63.27) v1(139.57,67.94) v1(139.7,55.37) v1(139.7,46.48) v1(139.7,42.67) v1(139.7,31.24) v1(139.7,27.43) v1(139.7,23.62) v1(139.7,16) v1(139.7,12.19) v1(139.7,9.65) v1(140.97,52.83) v1(140.97,45.21) v1(140.97,33.78) v1(140.97,29.97) v1(140.97,26.16) v1(140.97,22.35) v1(140.97,18.54) v1(140.97,14.73) v1(140.97,10.92) v1(140.97,0.64) v1(141.28,60.02) v1(142.24,59.18) v1(142.24,54.1) v1(142.24,46.48) v1(142.24,31.24) v1(142.24,27.43) v1(142.24,23.62) v1(142.24,19.81) v1(142.24,16) v1(142.24,12.19) v1(142.24,9.65) v1(142.88,0.64) v1(143.15,63.27) v1(143.38,67.94) v1(143.51,52.83) v1(143.51,49.02) v1(143.51,45.21) v1(143.51,41.4) v1(143.51,33.78) v1(143.51,29.97) v1(143.51,26.16) v1(143.51,22.35) v1(143.51,18.54) v1(143.51,14.73) v1(143.51,10.92) v1(144.63,7.58) v1(144.78,59.18) v1(144.78,55.37) v1(144.78,50.29) v1(144.78,42.67) v1(144.78,31.24) v1(144.78,27.43) v1(144.78,23.62) v1(144.78,19.81) v1(144.78,16) v1(144.78,12.19) v1(144.78,9.65) v1(144.78,0.64) v1(145.29,67.94) v1(146.05,43.94) v1(146.05,36.32) v1(146.05,28.7) v1(146.05,24.89) v1(146.05,13.46) v1(146.05,10.92) v1(146.69,0.64) v1(147.13,63.31) v1(147.19,67.94) v1(147.19,3.91) v1(147.32,59.18) v1(147.32,55.37) v1(147.32,50.29) v1(147.32,49.02) v1(147.32,45.21) v1(147.32,43.94) v1(147.32,40.13) v1(147.32,38.86) v1(147.32,33.78) v1(147.32,29.97) v1(147.32,28.7) v1(147.32,24.89) v1(147.32,23.62) v1(147.32,19.81) v1(147.32,18.54) v1(147.32,14.73) v1(147.32,12.19) v1(147.32,9.65) v1(147.92,44.86) v1(147.91,44.33) v1(147.96,39.72) v1(148.09,38.34) v1(148.59,51.56) v1(148.59,37.59) v1(148.59,36.32) v1(148.59,31.24) v1(148.59,27.43) v1(148.59,26.16) v1(148.59,22.35) v1(148.59,21.08) v1(148.59,17.27) v1(148.59,16) v1(148.59,12.19) v1(148.59,10.92) v1(148.59,0.64) v1(148.9,60.71) v1(149,66.56) v1(149.1,67.94) v1(149.86,59.18) v1(149.86,55.37) v1(149.86,54.1) v1(149.86,50.29) v1(149.86,49.02) v1(149.86,38.86) v1(149.86,29.97) v1(149.86,28.7) v1(149.86,24.89) v1(149.86,23.62) v1(149.86,19.81) v1(149.86,18.54) v1(149.86,14.73) v1(149.86,13.46) v1(149.86,9.65) v1(149.83,7.54) v1(150.42,38.09) v1(150.4,35.82) v1(150.37,0.64) v1(150.48,40.96) v1(150.62,57.96) v1(150.6,56.62) v1(150.59,52.93) v1(150.58,51.37) v1(150.6,47.9) v1(150.57,46.66) v1(151,67.94) v1(150.94,63.31) v1(151.4,3.95) v1(152.02,0.64) v1(153.67,67.06) v1(153.67,64.13) v1(153.67,62.36) v1(153.67,60.33) v1(153.67,58.55) v1(153.67,56.52) v1(153.67,54.74) v1(153.67,52.7) v1(153.67,50.93) v1(153.67,48.89) v1(153.67,47.12) v1(153.67,45.09) v1(153.67,43.31) v1(153.67,41.28) v1(153.67,39.5) v1(153.67,37.47) v1(153.67,35.69) v1(153.67,33.66) v1(153.67,31.88) v1(153.67,29.84) v1(153.67,28.07) v1(153.67,26.04) v1(153.67,24.26) v1(153.67,22.23) v1(153.67,20.45) v1(153.67,16.64) v1(153.67,14.61) v1(153.67,12.83) v1(153.67,10.8) v1(153.67,9.02) v1(153.67,6.99) v1(153.67,5.21) v1(153.67,3.18) v1(153.67,0.64) v2(31.06,45.06) v2(31.14,42.01) v2(32.16,44.48) v2(32.18,42.95) v2(32.23,43.51) v2(32.64,41.88) v2(33.1,41.83) v2(33.15,43.08) v2(33.48,45.19) v2(34.21,45.31) v2(34.16,41.58) v2(55.75,64.82) v2(55.75,64.47) v2(55.75,64.08) v2(57.25,64.82) v2(57.25,64.47) v2(57.25,64.08) v2(58.75,58.78) v2(58.75,58.42) v2(58.75,58.04) v2(59.26,58.78) v2(59.26,58.42) v2(59.26,58.04) v2(59.77,64.82) v2(59.77,64.47) v2(59.77,64.08) v2(60.25,64.85) v2(60.25,64.49) v2(60.25,64.11) v2(60.66,63.2) v2(60.66,62.18) v2(60.66,61.19) v2(61.04,63.2) v2(61.04,62.18) v2(61.04,61.19) v2(61.39,63.2) v2(61.39,62.18) v2(61.39,61.19) v3(0.46,57.45) v3(0.43,56.08) v3(0.71,40.31) v3(0.69,38.94) v3(0.71,32.05) v3(0.69,30.68) v3(0.71,21.64) v3(0.69,20.27) v3(1.32,7.57) v3(1.32,6.17) v3(1.39,56.77) v3(1.73,54.79) v3(1.7,53.42) v3(1.65,39.63) v3(1.65,31.37) v3(1.65,20.96) v3(1.98,29.64) v3(1.96,28.27) v3(2.31,56.13) v3(2.28,6.85) v3(2.34,57.48) v3(2.59,40.34) v3(2.57,38.99) v3(2.59,32.08) v3(2.57,30.73) v3(2.59,21.67) v3(2.57,20.32) v3(2.67,66.5) v3(2.67,65.07) v3(2.66,54.11) v3(2.79,13.67) v3(2.79,12.24) v3(2.82,4.78) v3(2.82,3.38) v3(2.92,28.96) v3(3.2,7.54) v3(3.23,6.17) v3(3.61,54.81) v3(3.58,53.47) v3(3.64,65.79) v3(3.77,12.96) v3(3.77,4.06) v3(3.86,29.67) v3(3.84,28.32) v3(4.6,66.47) v3(4.6,65.07) v3(4.57,17.86) v3(4.57,16.43) v3(4.72,13.64) v3(4.72,12.24) v3(4.72,4.75) v3(4.7,3.38) v3(4.78,56.69) v3(4.75,55.32) v3(4.78,31.67) v3(4.75,30.3) v3(5.41,21.51) v3(5.38,20.14) v3(5.55,17.15) v3(5.71,56.01) v3(5.71,30.99) v3(5.84,63.32) v3(5.84,61.9) v3(6.17,40.31) v3(6.15,38.94) v3(6.35,20.83) v3(6.5,17.83) v3(6.5,16.43) v3(6.63,55.37) v3(6.63,30.35) v3(6.65,56.72) v3(6.65,31.7) v3(6.82,62.62) v3(6.91,46.3) v3(6.93,47.68) v3(7.11,39.63) v3(7.19,29.01) v3(7.16,27.64) v3(7.29,21.54) v3(7.26,20.19) v3(7.77,63.3) v3(7.77,61.9) v3(7.87,47) v3(8.03,38.99) v3(8.08,57.58) v3(8.05,56.21) v3(8.05,40.34) v3(8.13,28.33) v3(8.2,66.47) v3(8.18,65.1) v3(8.31,12.27) v3(8.31,4.78) v3(8.31,3.38) v3(8.33,13.64) v3(8.81,47.7) v3(8.79,46.36) v3(9.01,56.9) v3(9.07,29.03) v3(9.04,27.69) v3(9.14,65.79) v3(9.27,12.96) v3(9.27,4.06) v3(9.96,57.61) v3(9.93,56.26) v3(10.08,66.5) v3(10.06,65.15) v3(10.11,17.83) v3(10.08,16.46) v3(10.21,13.67) v3(10.19,12.32) v3(10.19,4.75) v3(10.21,3.38) v3(11,22.4) v3(10.97,21.03) v3(11.05,17.15) v3(11.38,63.3) v3(11.35,61.93) v3(11.94,21.72) v3(11.99,17.86) v3(11.96,16.51) v3(11.99,3.25) v3(11.99,1.85) v3(12.32,62.62) v3(12.78,66.6) v3(12.75,65.23) v3(12.88,22.43) v3(12.85,21.08) v3(12.95,12.14) v3(12.95,10.72) v3(12.95,2.53) v3(13.26,63.32) v3(13.23,61.98) v3(13.51,13.79) v3(13.54,15.16) v3(13.71,65.92) v3(13.93,11.44) v3(13.87,3.23) v3(13.89,1.85) v3(14.48,14.48) v3(14.66,66.62) v3(14.63,65.28) v3(14.81,60.12) v3(14.78,58.75) v3(14.88,12.12) v3(14.88,10.72) v3(15.19,32.31) v3(15.16,30.94) v3(15.32,54.79) v3(15.29,53.42) v3(15.42,15.19) v3(15.39,13.84) v3(15.57,36.63) v3(15.54,35.26) v3(15.7,24.05) v3(15.67,22.68) v3(15.75,59.44) v3(15.8,5.03) v3(15.8,3.63) v3(16.13,31.63) v3(16.25,54.11) v3(16.51,35.95) v3(16.69,60.15) v3(16.66,58.8) v3(16.71,50.22) v3(16.69,48.84) v3(16.63,23.37) v3(16.76,4.31) v3(17.07,32.33) v3(17.04,30.99) v3(17.2,54.81) v3(17.17,53.47) v3(17.42,35.31) v3(17.45,36.65) v3(17.6,28.12) v3(17.58,26.75) v3(17.58,24.08) v3(17.55,22.73) v3(17.65,49.54) v3(17.68,5) v3(17.7,3.63) v3(18.36,58.47) v3(18.34,57.1) v3(18.49,12.12) v3(18.47,10.74) v3(18.59,50.24) v3(18.57,48.89) v3(18.54,27.44) v3(19,36.5) v3(18.97,35.13) v3(19.23,60.4) v3(19.25,61.77) v3(19.3,57.79) v3(19.43,11.44) v3(19.48,28.14) v3(19.46,26.8) v3(19.94,35.82) v3(20.19,61.09) v3(20.22,57.15) v3(20.24,58.5) v3(20.37,12.14) v3(20.35,10.8) v3(20.5,3.51) v3(20.5,2.11) v3(20.88,36.53) v3(20.85,35.18) v3(21.11,60.45) v3(21.13,61.8) v3(21.29,27.99) v3(21.26,26.62) v3(21.46,2.79) v3(21.97,17.98) v3(21.97,16.56) v3(22.22,27.31) v3(22.38,3.48) v3(22.4,2.11) v3(22.48,23.95) v3(22.48,22.53) v3(22.66,14.17) v3(22.66,12.78) v3(22.86,66.5) v3(22.86,65.07) v3(22.95,17.28) v3(23.16,28.02) v3(23.14,26.67) v3(23.45,23.25) v3(23.62,13.46) v3(23.83,65.79) v3(23.93,34.87) v3(23.9,17.96) v3(23.9,16.56) v3(23.95,36.25) v3(24.21,50.6) v3(24.18,49.23) v3(24.31,52.91) v3(24.33,54.28) v3(24.41,23.93) v3(24.41,22.53) v3(24.54,14.15) v3(24.56,12.78) v3(24.79,66.47) v3(24.79,65.07) v3(24.82,31.06) v3(24.89,35.57) v3(24.84,32.44) v3(25.14,49.92) v3(25.15,28.91) v3(25.15,27.48) v3(25.27,53.6) v3(25.81,34.92) v3(25.78,31.76) v3(25.83,36.27) v3(26.09,50.62) v3(26.06,49.28) v3(26.12,28.2) v3(26.16,63.32) v3(26.16,61.9) v3(26.21,54.31) v3(26.19,52.96) v3(26.72,32.46) v3(26.7,31.12) v3(27.08,28.88) v3(27.08,27.48) v3(27.14,62.62) v3(27.51,17.96) v3(27.48,16.59) v3(28.02,23.93) v3(27.99,22.56) v3(28.09,63.3) v3(28.09,61.9) v3(28.4,66.47) v3(28.37,65.1) v3(28.45,17.28) v3(28.78,57.33) v3(28.75,55.96) v3(28.95,23.25) v3(29.33,65.79) v3(29.39,17.98) v3(29.36,16.64) v3(29.72,56.65) v3(29.9,23.95) v3(29.87,22.61) v3(30.28,66.5) v3(30.25,65.15) v3(30.66,57.35) v3(30.63,56.01) v3(30.68,28.88) v3(30.66,27.51) v3(31.62,28.2) v3(31.7,63.3) v3(31.67,61.93) v3(31.7,59.87) v3(31.67,58.5) v3(32.39,25.73) v3(32.39,24.31) v3(32.56,28.91) v3(32.54,27.56) v3(32.64,62.62) v3(32.64,59.19) v3(33.36,25.02) v3(33.58,63.32) v3(33.55,61.98) v3(33.58,59.89) v3(33.55,58.55) v3(34.32,25.7) v3(34.32,24.31) v3(35.61,64.85) v3(35.64,66.22) v3(36.57,65.54) v3(37.52,66.24) v3(37.49,64.9) v3(37.92,25.7) v3(37.9,24.33) v3(38.3,45.37) v3(38.3,44.05) v3(38.3,42.74) v3(38.3,41.42) v3(38.3,40.11) v3(38.86,25.02) v3(39.61,46.68) v3(39.61,44.05) v3(39.61,42.74) v3(39.61,41.42) v3(39.61,38.79) v3(39.8,25.73) v3(39.78,24.38) v3(40.93,46.68) v3(40.93,45.37) v3(40.93,42.74) v3(40.93,40.11) v3(40.93,38.79) v3(42.24,46.68) v3(42.24,45.37) v3(42.24,44.05) v3(42.24,41.42) v3(42.24,40.11) v3(42.24,38.79) v3(43.56,46.68) v3(43.56,45.37) v3(43.56,42.74) v3(43.56,41.42) v3(43.56,40.11) v3(44.87,46.68) v3(44.87,44.05) v3(44.87,42.74) v3(44.87,41.42) v3(44.87,38.79) v3(46.19,46.68) v3(46.19,44.05) v3(46.19,42.74) v3(46.19,41.42) v3(66.03,18.23) v3(67.05,18.23) v3(67.05,17.21) v3(67.05,16.2) v3(68.06,18.23) v3(68.06,16.2) v3(85.14,14.51) v3(85.14,13.81) v3(85.14,13.11) v3(85.14,12.41) v3(85.14,11.71) v3(85.84,13.81) v3(85.84,13.11) v3(85.84,12.41) v3(85.84,11.71) v3(86.54,14.51) v3(86.54,13.81) v3(86.54,13.11) v3(86.54,12.41) v3(86.54,11.71) v3(87.24,14.51) v3(87.24,13.81) v3(87.24,13.11) v3(87.24,12.41) v3(87.24,11.71) v3(87.94,14.51) v3(87.94,13.81) v3(87.94,13.11) v3(87.94,12.41) v3(87.94,11.71) v3(109.7,10.54) v3(109.7,9.53) v3(110.72,10.54) v3(110.72,9.53) v3(122.38,9.35) v3(122.38,8.33) v3(123.39,9.35) v3(124.41,9.35) v3(130.91,9.22) v3(130.91,8.2) v3(130.91,7.19) v3(131.93,9.22) v3(139.7,19.81) v3(140.97,56.64) v4(6.73,59.31) v4(7.11,24) v4(7.87,26.16) v4(8.51,59.18) v4(9.02,24.26) v4(9.78,60.96) v4(9.78,26.8) v4(10.29,58.29) v4(10.67,24.89) v4(11.05,27.94) v4(11.43,60.07) v4(11.43,56.9) v4(11.81,29.34) v4(11.94,55.25) v4(12.07,53.34) v4(12.07,51.82) v4(12.07,50.55) v4(12.04,33.15) v4(12.04,31.27) v4(12.19,26.04) v4(12.7,58.8) v4(13.34,27.43) v4(13.72,56.9) v4(14.1,55.25) v4(14.1,53.47) v4(14.1,51.82) v4(14.1,33.27) v4(14.1,29.34) v4(14.22,31.5) v4(18.03,42.8) v4(21.84,43.37) v4(21.84,42.74) v4(21.84,41.97) v4(22.61,43.37) v4(22.61,42.74) v4(22.61,41.97) v4(23.37,43.37) v4(23.37,42.74) v4(23.37,41.97) v4(24.77,44.96) v4(24.77,40.64) v4(25.53,40.11) v4(25.55,45.34) v4(26.47,46.51) v4(26.59,39.04) v4(26.72,42.24) v4(26.75,43.18) v4(27.13,49.61) v4(27.1,48.41) v4(27.13,47.09) v4(27.18,50.93) v4(27.15,38.35) v4(27.15,37.06) v4(27.18,35.81) v4(27.18,34.54) v4(27.69,52.58) v4(27.69,33.02) v4(28.51,42.74) v4(28.68,40.44) v4(28.96,53.21) v4(29.34,49.66) v4(29.34,48.39) v4(29.34,47.12) v4(29.34,39.62) v4(29.34,38.35) v4(29.34,37.08) v4(29.34,35.81) v4(29.34,31.75) v4(29.97,42.74) v4(30.1,53.85) v4(30.1,50.29) v4(31.24,31.88) v4(31.37,53.72) v4(31.37,50.42) v4(32,34.92) v4(33.15,53.72) v4(34.29,31.88) v4(34.42,35.05) v4(35.31,53.72) v4(37.47,53.59) v4(37.47,34.92) v4(38.99,51.05) v4(38.99,34.42) v4(40.26,32.89) v4(40.89,52.2) v4(41.15,49.91) v4(41.15,35.56) v4(41.28,34.04) v4(91.47,59.39) v4(91.47,57.35) v4(91.47,56.34) v4(92.48,59.39) v4(92.48,58.37) v4(92.48,57.35) v4(92.48,56.34) v4(92.48,55.32) v4(93.5,60.4) v4(93.5,59.39) v4(93.5,58.37) v4(93.5,57.35) v4(93.5,56.34) v4(93.5,55.32) v4(94.52,60.4) v4(94.52,59.39) v4(94.52,58.37) v4(94.52,57.35) v4(94.52,56.34) v4(94.52,55.32) v4(95.53,60.4) v4(95.53,59.39) v4(95.53,58.37) v4(95.53,57.35) v4(95.53,56.34) v4(95.53,55.32) v4(95.53,54.31) v4(96.55,60.4) v4(96.55,59.39) v4(96.55,58.37) v4(96.55,57.35) v4(96.55,56.34) v4(96.55,55.32) v4(96.55,54.31) v4(97.56,60.4) v4(97.56,58.37) v4(97.56,57.35) v4(97.56,56.34) v4(97.56,55.32) v5(61.95,55.65) v5(61.96,51.82) v5(63.16,51.52) v5(63.58,55.96) v5(65.36,51.62) v5(66.29,55.78) v5(66.26,54.72) v5(66.26,52.72) v6(57.51,61.95) v6(57.51,60.93) v6(59.54,59.92)
